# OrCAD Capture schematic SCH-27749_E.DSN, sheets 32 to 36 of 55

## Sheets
32 DDR #2 DIMM: size C
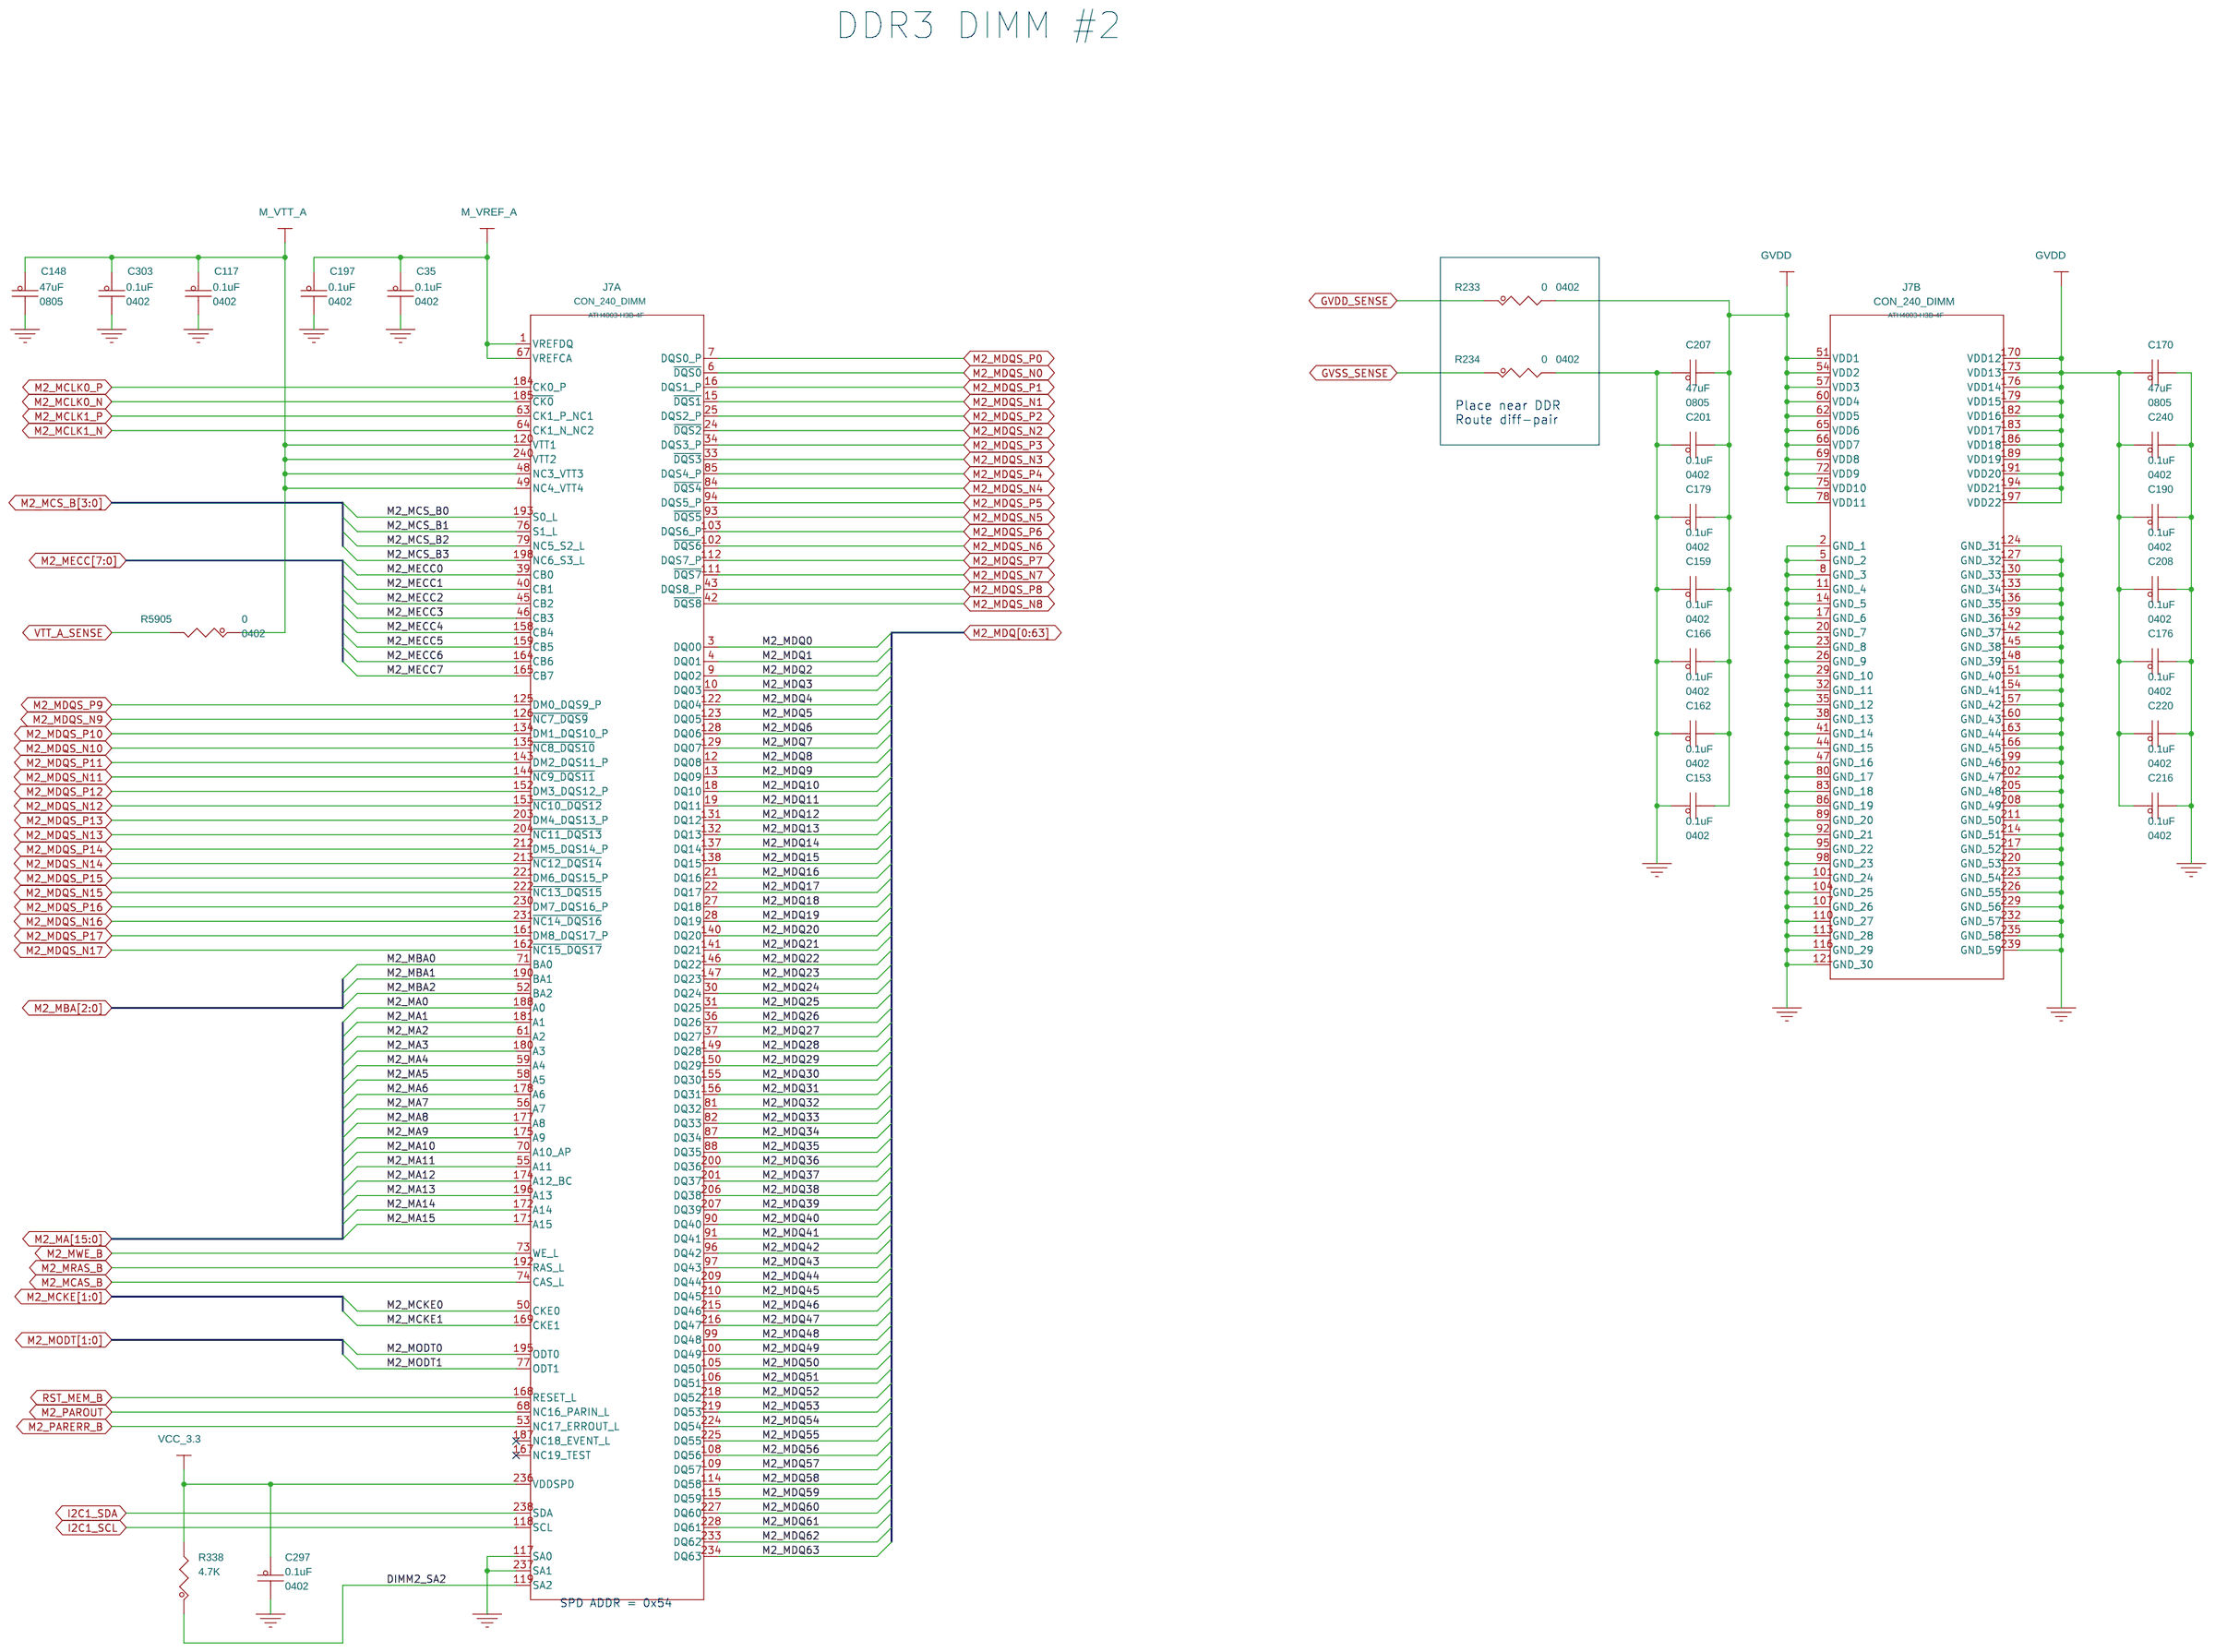
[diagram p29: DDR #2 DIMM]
33 DDR #3 DIMM: size C
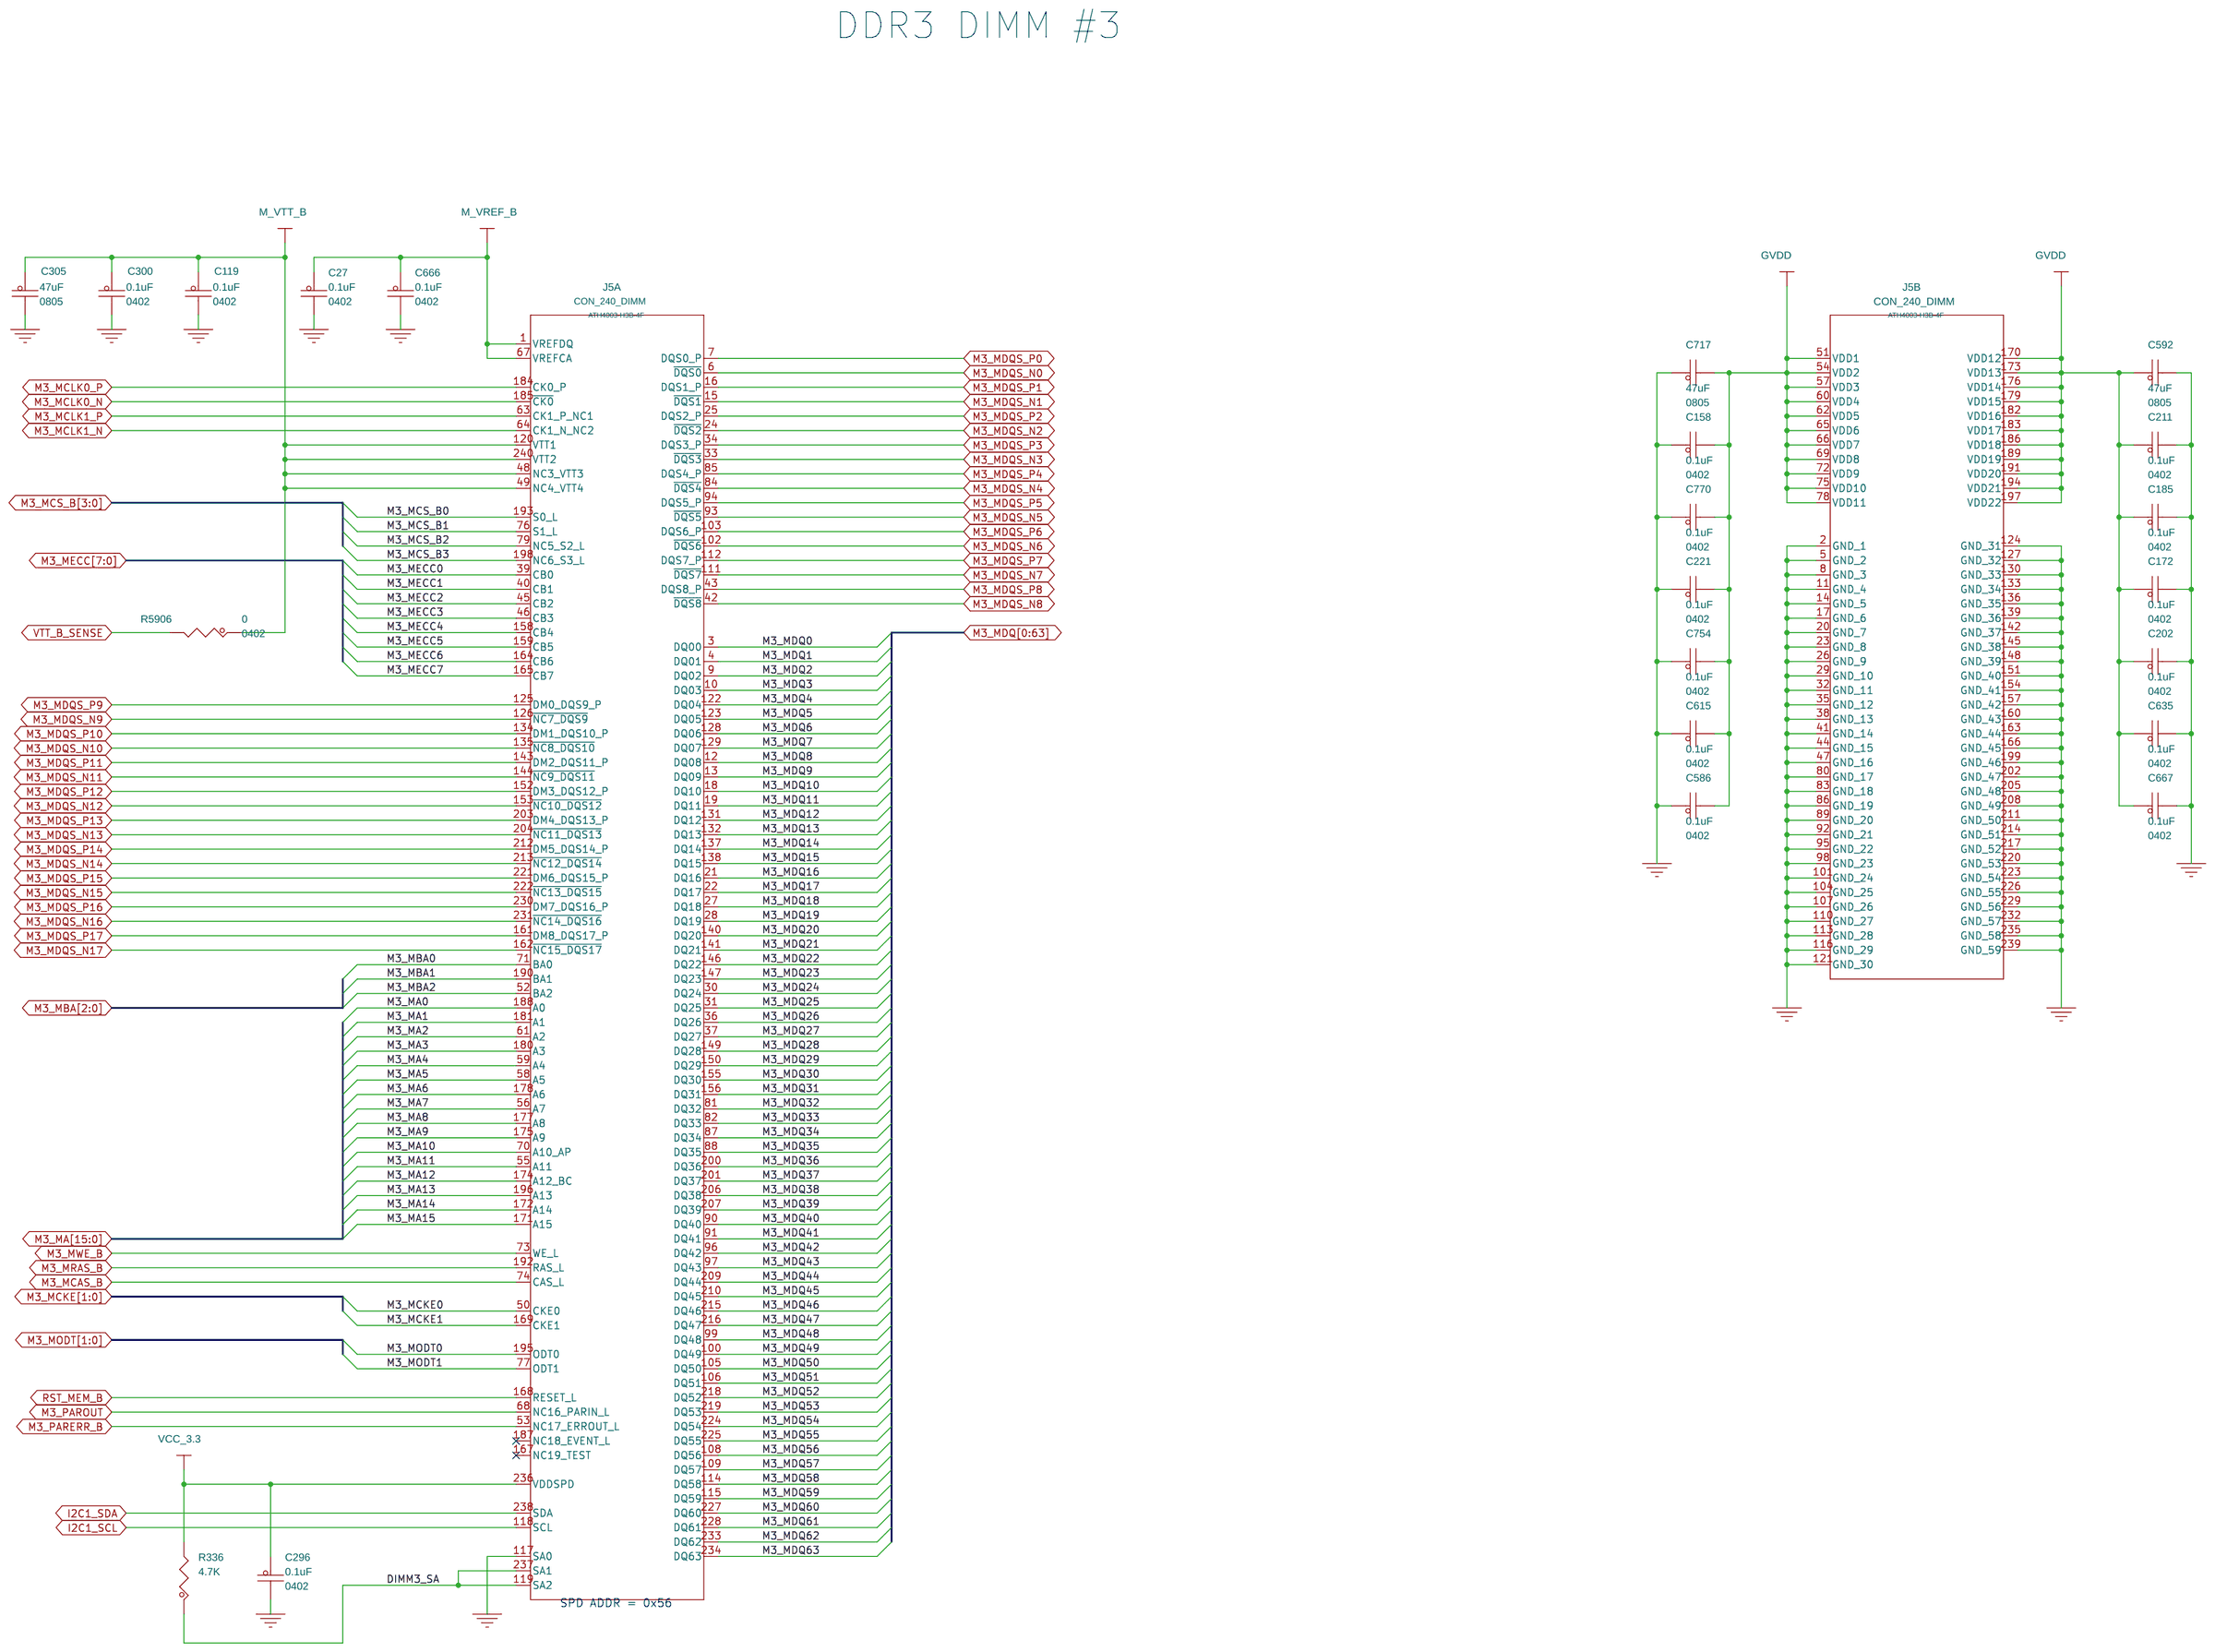
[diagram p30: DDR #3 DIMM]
34 T4240 Local Bus Block: size C
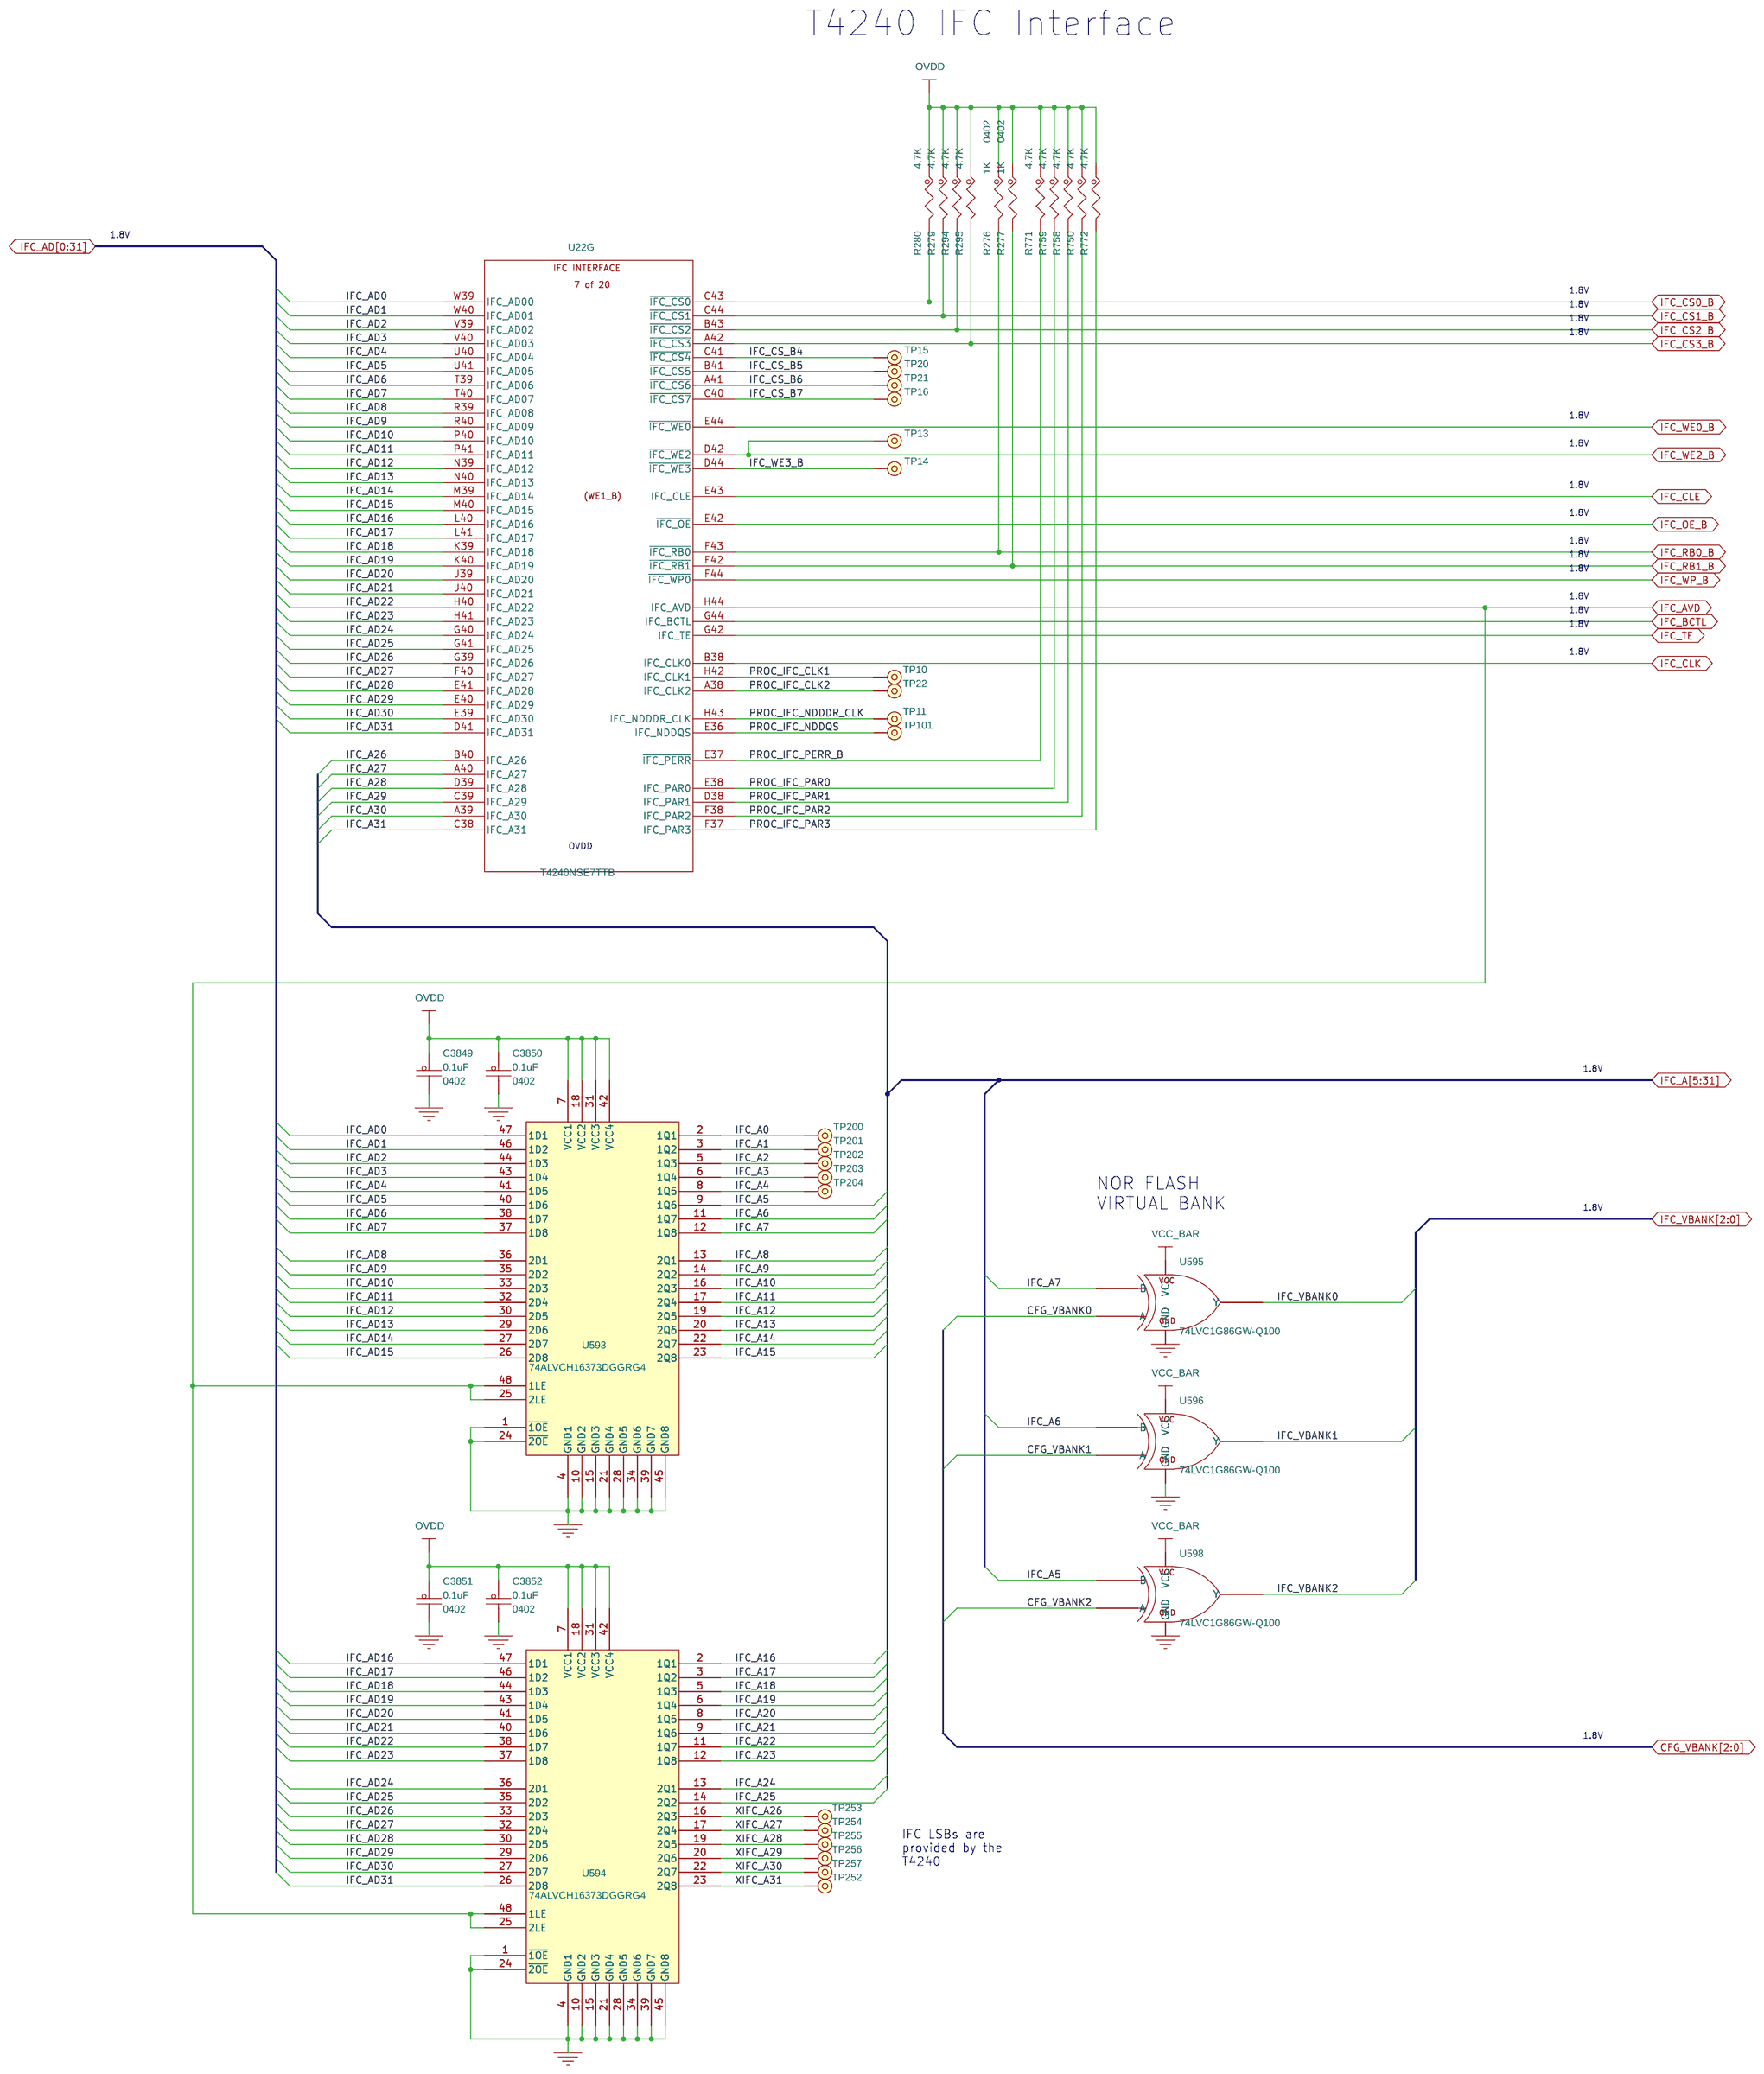
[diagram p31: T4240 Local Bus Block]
35 NOR & NAND Flash: size C
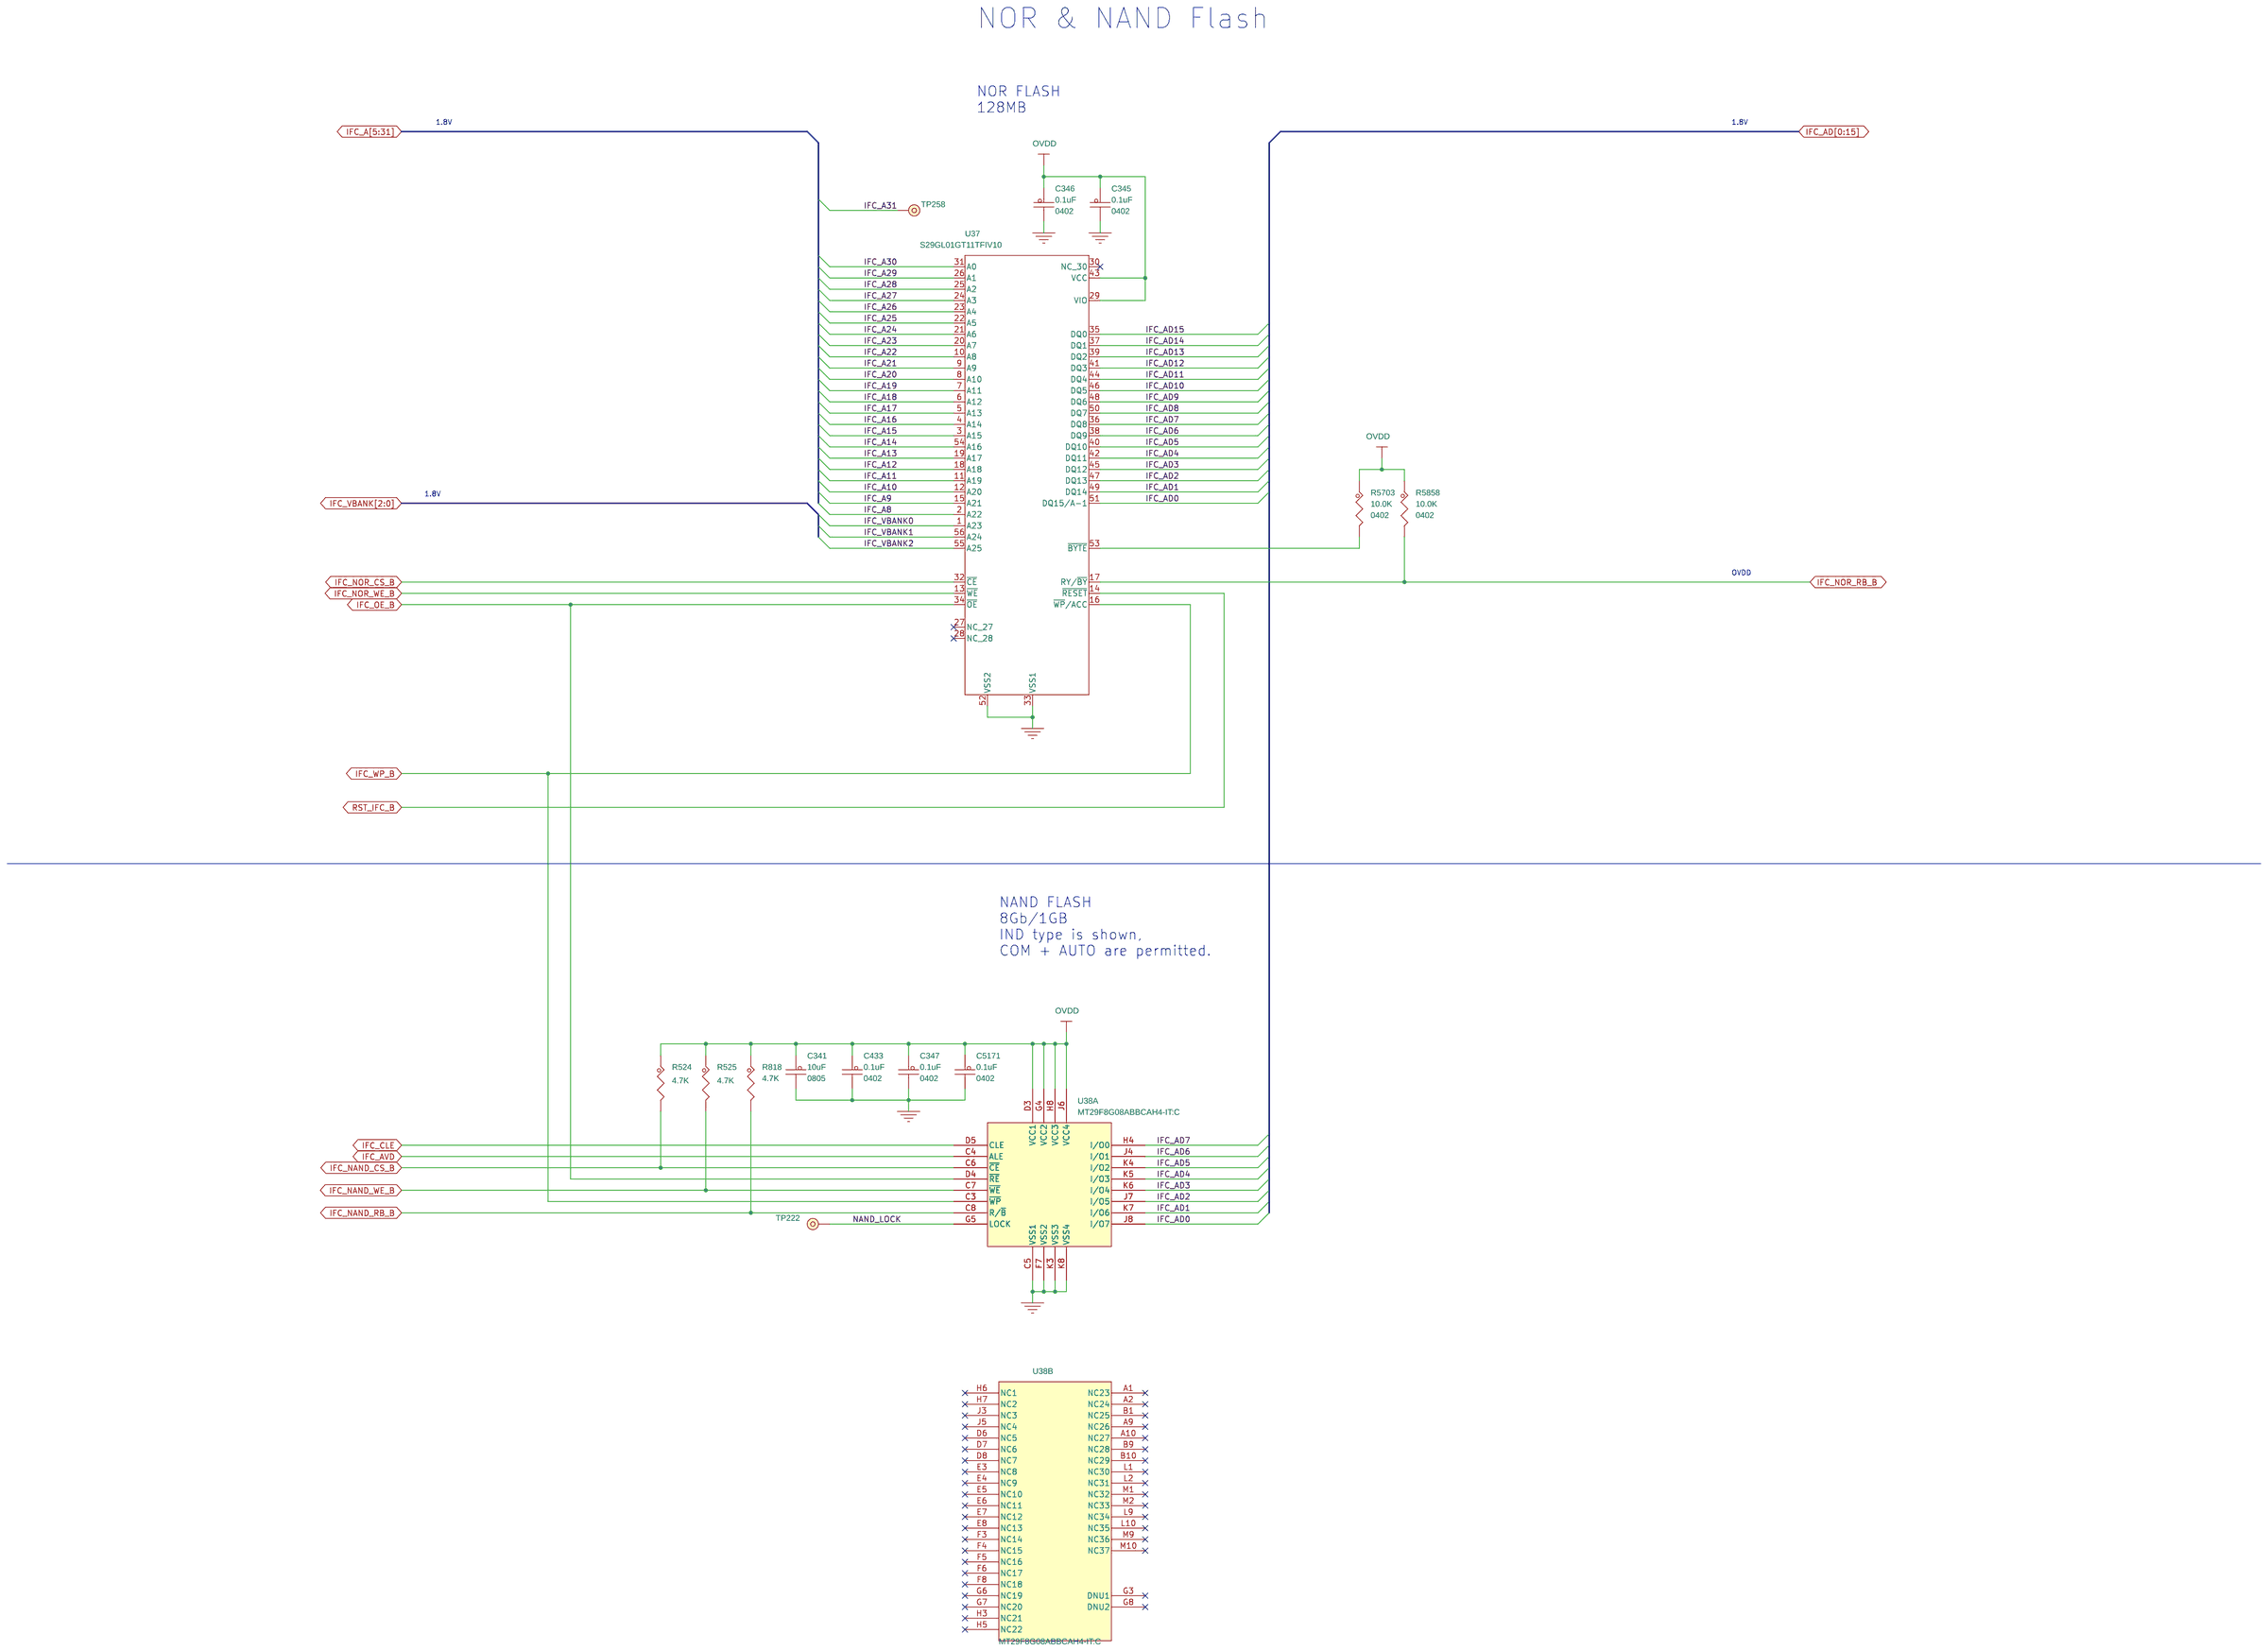
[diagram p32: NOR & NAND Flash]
36 T4240 SPI / SDHC Port: size C
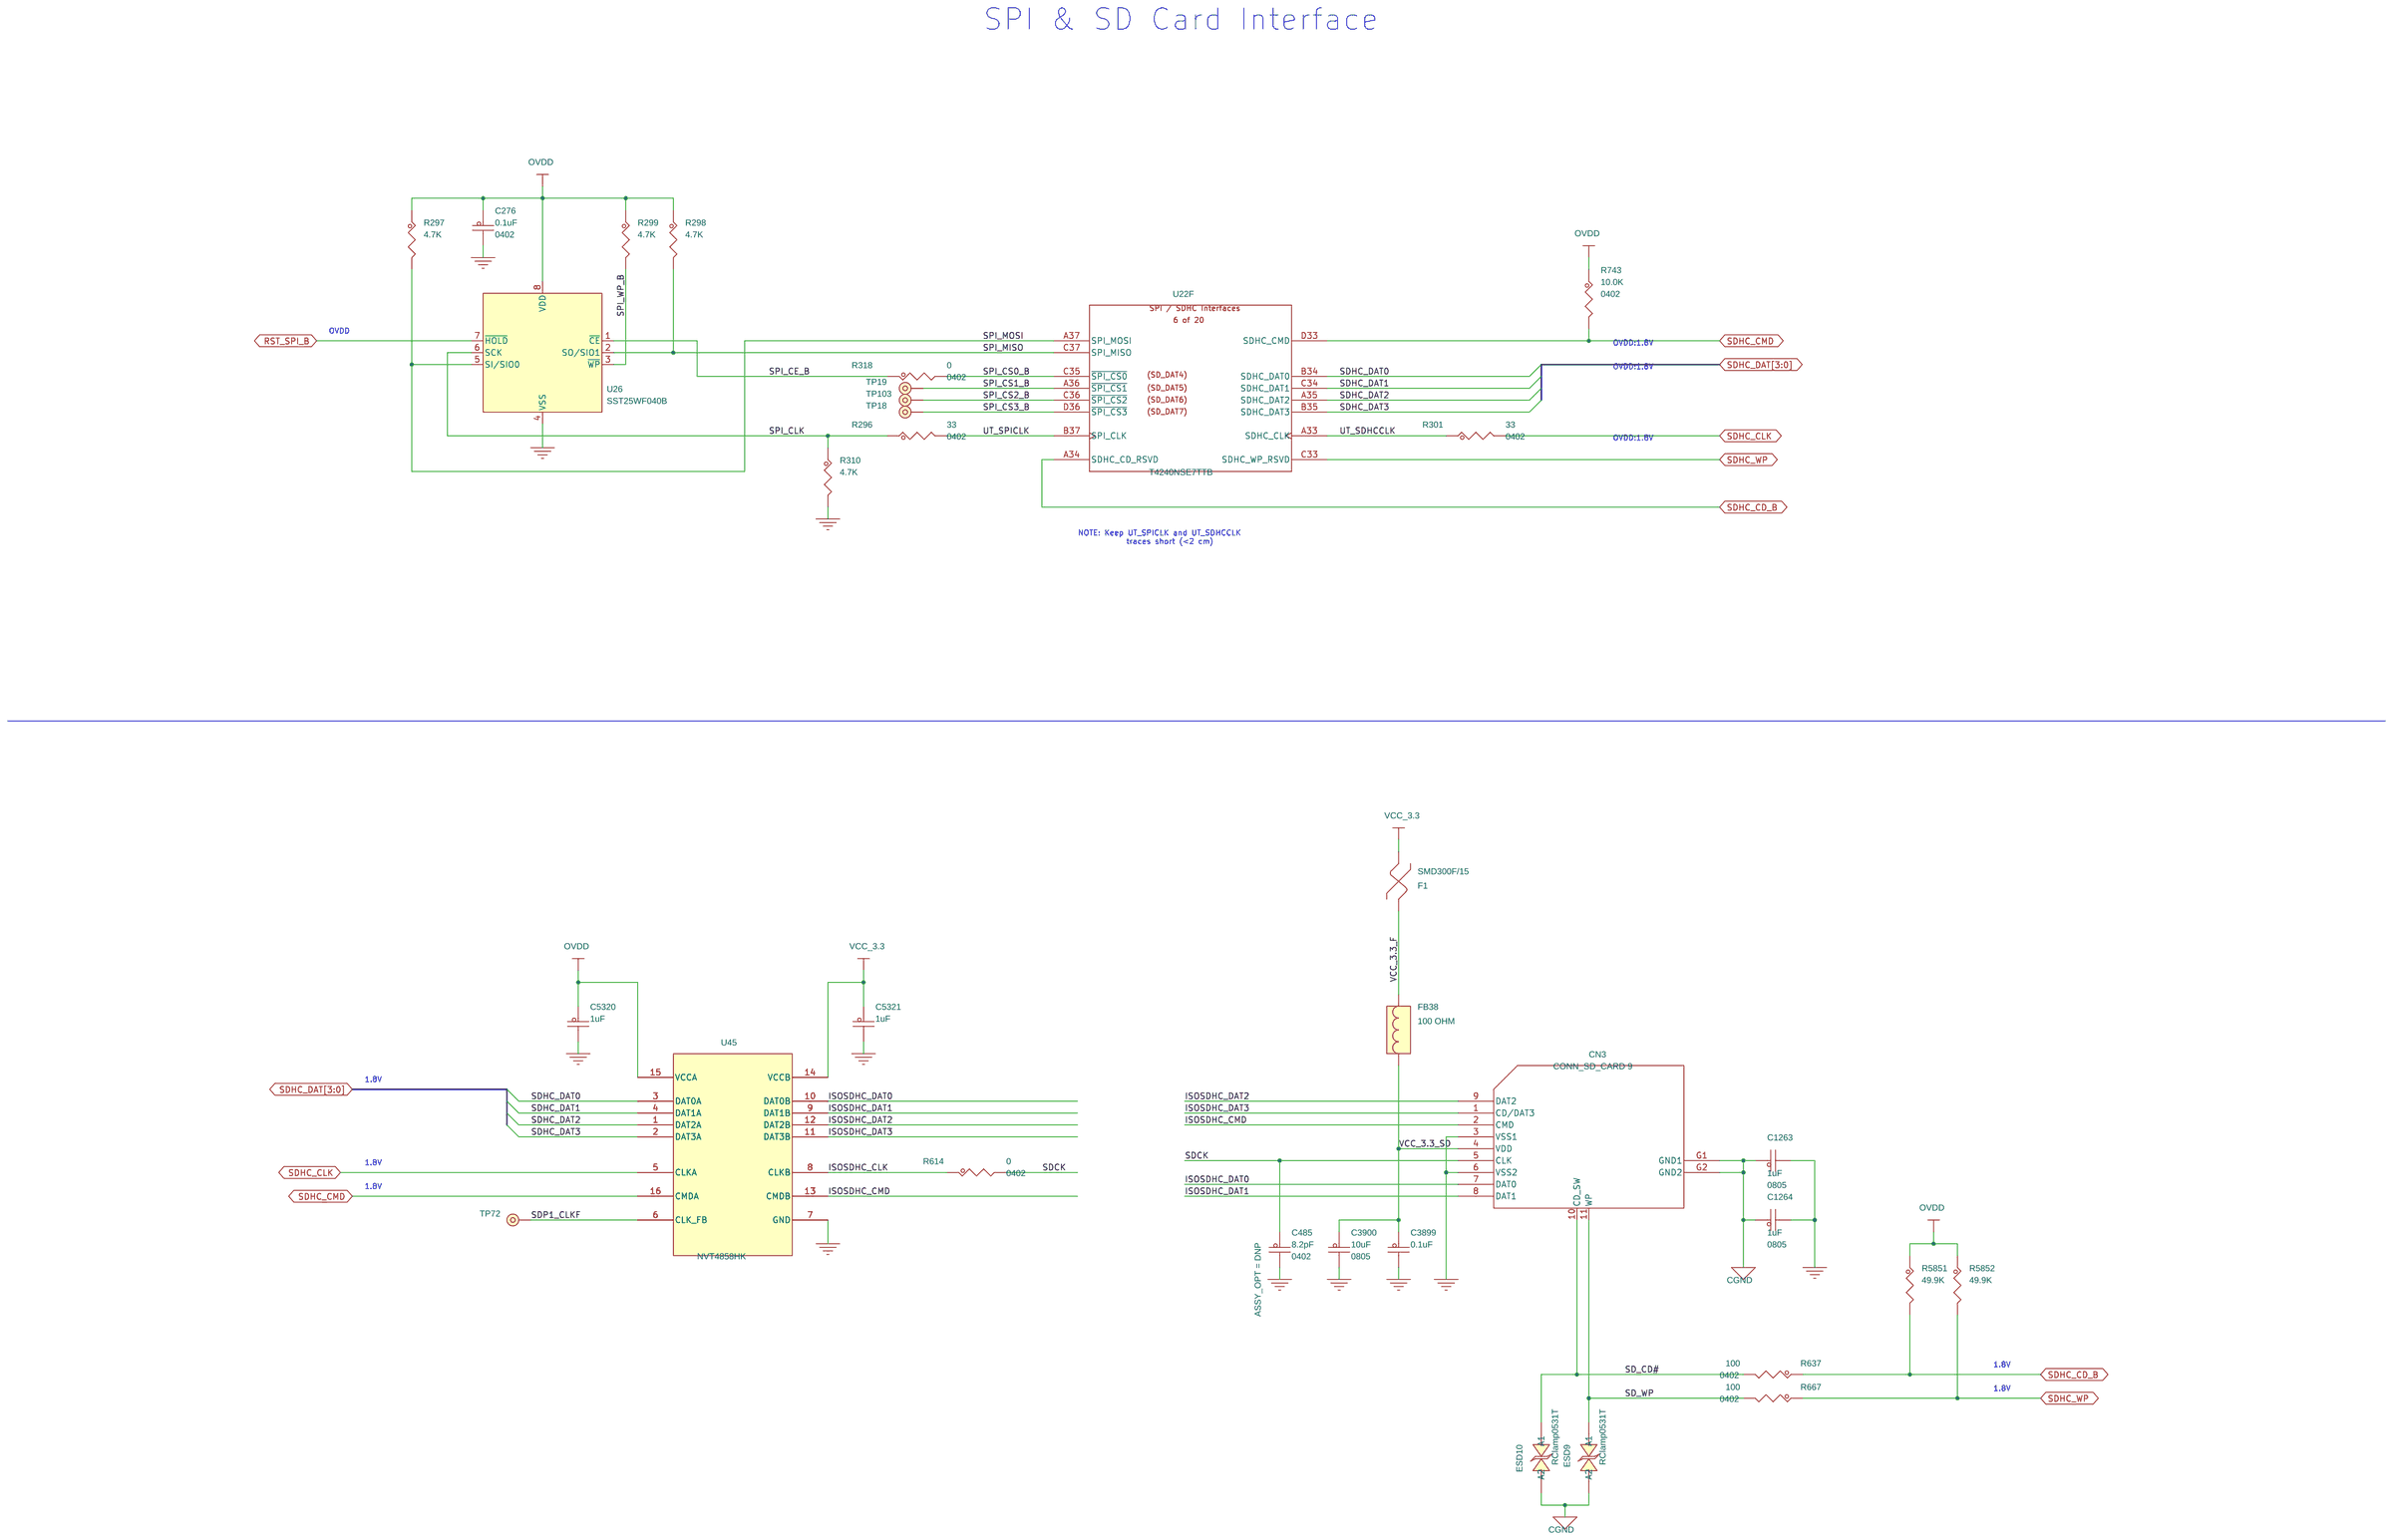
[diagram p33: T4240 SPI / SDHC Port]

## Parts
sheet DDR #2 DIMM
C35  0.1uF  [CC0402_HD]
C117  0.1uF  [CC0402_HD]
C148  47uF  [CC0805_OV]
C153  0.1uF  [CC0402_HD]
C159  0.1uF  [CC0402_HD]
C162  0.1uF  [CC0402_HD]
C166  0.1uF  [CC0402_HD]
C170  47uF  [CC0805_OV]
C176  0.1uF  [CC0402_HD]
C179  0.1uF  [CC0402_HD]
C190  0.1uF  [CC0402_HD]
C197  0.1uF  [CC0402_HD]
C201  0.1uF  [CC0402_HD]
C207  47uF  [CC0805_OV]
C208  0.1uF  [CC0402_HD]
C216  0.1uF  [CC0402_HD]
C220  0.1uF  [CC0402_HD]
C240  0.1uF  [CC0402_HD]
C297  0.1uF  [CC0402_HD]
C303  0.1uF  [CC0402_HD]
J7  CON_240_DIMM  [CON_240_DDR3_DIMM_SKT]  (sections A,B)
R233  0  [RC0402_25]
R234  0  [RC0402_25]
R338  4.7K  [RC0402_25]
R5905  0  [RC0402_25]
sheet DDR #3 DIMM
C27  0.1uF  [CC0402_HD]
C119  0.1uF  [CC0402_HD]
C158  0.1uF  [CC0402_HD]
C172  0.1uF  [CC0402_HD]
C185  0.1uF  [CC0402_HD]
C202  0.1uF  [CC0402_HD]
C211  0.1uF  [CC0402_HD]
C221  0.1uF  [CC0402_HD]
C296  0.1uF  [CC0402_HD]
C300  0.1uF  [CC0402_HD]
C305  47uF  [CC0805_OV]
C586  0.1uF  [CC0402_HD]
C592  47uF  [CC0805_OV]
C615  0.1uF  [CC0402_HD]
C635  0.1uF  [CC0402_HD]
C666  0.1uF  [CC0402_HD]
C667  0.1uF  [CC0402_HD]
C717  47uF  [CC0805_OV]
C754  0.1uF  [CC0402_HD]
C770  0.1uF  [CC0402_HD]
J5  CON_240_DIMM  [CON_240_DDR3_DIMM_SKT]  (sections A,B)
R336  4.7K  [RC0402_25]
R5906  0  [RC0402_25]
sheet NOR & NAND Flash
C341  10uF  [CC0603_OV]
C345  0.1uF  [CC0402_HD]
C346  0.1uF  [CC0402_HD]
C347  0.1uF  [CC0402_HD]
C433  0.1uF  [CC0402_HD]
C5171  0.1uF  [CC0402_HD]
R524  4.7K  [RC0402_25]
R525  4.7K  [RC0402_25]
R818  4.7K  [RC0402_25]
R5703  10.0K  [RC0402_25]
R5858  10.0K  [RC0402_25]
TP222  TPAD_020  [tpad_020_top]
TP258  TPAD_020  [tpad_020_top]
U37  S29GL01GT11TFIV10  [TSOP56_0P5_14X18]
U38  MT29F8G08ABBCAH4-IT:C  [vfbga63_0p8_9x11]  (sections A,B)
sheet T4240 DDR Controller #2
U22  T4240NSE7TTB  [BGA1932_1MM_45X45MM]  (sections A,B,C,D,E,F,G,H,I,J,K,L,M,N,O,P,Q,R,S,T)
sheet T4240 Local Bus Block
C3849  0.1uF  [CC0402_HD]
C3850  0.1uF  [CC0402_HD]
C3851  0.1uF  [CC0402_HD]
C3852  0.1uF  [CC0402_HD]
R276  1K  [RC0402_25]
R277  1K  [RC0402_25]
R279  4.7K  [RC0402_25]
R280  4.7K  [RC0402_25]
R294  4.7K  [RC0402_25]
R295  4.7K  [RC0402_25]
R750  4.7K  [RC0402_25]
R758  4.7K  [RC0402_25]
R759  4.7K  [RC0402_25]
R771  4.7K  [RC0402_25]
R772  4.7K  [RC0402_25]
TP10  TPAD_020  [tpad_020_top]
TP11  TPAD_020  [tpad_020_top]
TP13  TPAD_020  [tpad_020_top]
TP14  TPAD_020  [tpad_020_top]
TP15  TPAD_020  [tpad_020_top]
TP16  TPAD_020  [tpad_020_top]
TP20  TPAD_020  [tpad_020_top]
TP21  TPAD_020  [tpad_020_top]
TP22  TPAD_020  [tpad_020_top]
TP101  TPAD_020  [tpad_020_top]
TP200  TPAD_020  [tpad_020_top]
TP201  TPAD_020  [tpad_020_top]
TP202  TPAD_020  [tpad_020_top]
TP203  TPAD_020  [tpad_020_top]
TP204  TPAD_020  [tpad_020_top]
TP252  TPAD_020  [tpad_020_top]
TP253  TPAD_020  [tpad_020_top]
TP254  TPAD_020  [tpad_020_top]
TP255  TPAD_020  [tpad_020_top]
TP256  TPAD_020  [tpad_020_top]
TP257  TPAD_020  [tpad_020_top]
U593  74ALVCH16373DGGRG4  [TSSOP48_PH]
U594  74ALVCH16373DGGRG4  [TSSOP48_PH]
U595  74LVC1G86GW-Q100  [SC70-5]
U596  74LVC1G86GW-Q100  [SC70-5]
U598  74LVC1G86GW-Q100  [SC70-5]
sheet T4240 SPI / SDHC Port
C276  0.1uF  [CC0402_HD]
C485  8.2pF  [CC0402_25]
C1263  1uF  [CC0603_OV]
C1264  1uF  [CC0603_OV]
C3899  0.1uF  [CC0402_HD]
C3900  10uF  [CC0603_OV]
C5320  1uF  [CC0402_HD]
C5321  1uF  [CC0402_HD]
CN3  CONN_SD_CARD 9  [con_sdcard_28p9x29_sm_ra]
ESD9  RClamp0531T  [diode_bidir_0402]
ESD10  RClamp0531T  [diode_bidir_0402]
F1  SMD300F/15  [FUSE_SMD050]
FB38  100 OHM  [IND_0805]
R296  33  [RC0402_25]
R297  4.7K  [RC0402_25]
R298  4.7K  [RC0402_25]
R299  4.7K  [RC0402_25]
R301  33  [RC0402_25]
R310  4.7K  [RC0402_25]
R318  0  [RC0402_25]
R614  0  [RC0402_25]
R637  100  [RC0402_25]
R667  100  [RC0402_25]
R743  10.0K  [RC0402_25]
R5851  49.9K  [RC0402_25]
R5852  49.9K  [RC0402_25]
TP18  TPAD_020  [tpad_020_top]
TP19  TPAD_020  [tpad_020_top]
TP72  TPAD_020  [tpad_020_top]
TP103  TPAD_020  [tpad_020_top]
U26  SST25WF040B  [SO8_1P27_4X5]
U45  NVT4858HK  [xqfn16_0p4_2p7x1p9]

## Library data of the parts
C27 C35 C117 C119 C153 C158 C159 C162 C166 C172 C176 C179 C185 C190 C197 C201 C202 C208 C211 C216 C220 C221 C240 C276 C296 C297 C300 C303 C345-C347 C433 C586 C615 C635 C666 C667 C754 C770 C3849-C3852 C5171 = CAP_NP: CAP CER 0.1uF 16V 10% X7R AEC-Q200 0402; AGILE_PN: 150-79025; CAD_APPROVED: Yes; FPLIST: CC0402_25,CC0402_HD,0402_CC,capc0402_l; HEIGHT: 0.55MM; MFG_NAME01: MURATA; MFG_PN01: GCM155R71C104KA55D; Package: 0402; Package Size: 0402; Package Type: ø180mm Reel PAPER; Part Number: 4CC104B163X00; Product Name: (H)MLCC 0.1uF/16V +-10% 0402 X7R; ROHS: Yes; Rated Voltage: 16V; Temp Range: -55C to +125C; Tolerance: 10%
C148 C170 C207 C305 C592 C717 = CAP_NP: CAP CER 47uF 6.3V 20% X5R AEC-Q200 0805; AGILE_PN: 150-80462; CAD_APPROVED: Yes; FPLIST: CC0805_OV,CC0805,0805_CC; HEIGHT: 1.45MM; MFG_NAME01: MURATA; MFG_PN01: GRT21BR60J476ME13L; Package: 0805; Package Size: 2x1.25MM; Package Type: 0805; Part Number: 4CC476D631X00; Product Name: (H)MLCC 47uF/6.3V +-20% 0805 X5R; ROHS: Yes; Rated Voltage: 6.3V; Temp Range: -55C to +85C; Tolerance: 20%
J7 = DDR3_240P: CON 240 DIMM DDR3 1.5V SKT TH 1MM SP 910H .125 THK PCB AU 125L; AGILE_PN: 210-77672; CAD_APPROVED: Yes; CDS_LIB: fcl_connector; COMP_HEIGHT: 23.10 MM; CPN: TMP-WF-6058; CaptureCellPackProp: DDR3_240PA; DRAWING: @EXPEDITION_LIB.EXPEDITION(SCH_1):PAGE33; GROUP: DIMM4; HEIGHT: 23.10 MM; LOCATION: J22; MFG_NAME: FOXCONN; MFG_NAME01: FOXCONN; MFG_PN: ATH4003-H3B-4F; MFG_PN01: ATH4003-H3B-4F; PHYS_PAGE: 33; Part Number: 4SRD324006X00; Product Name: DDR3 DIMM SOCKET 240PIN FOXCONN:ATH4017-P3B-4F; ROHS: Yes; ROT: 0; XY: (-5700,2625)
R233 R234 R318 R614 R5905 R5906 = RES: RES MF ZERO OHM 1/10W -- 0402; AGILE_PN: 470-79965; CAD_APPROVED: Yes; FPLIST: RC0402_25,RC0402_HD,RC0402_X2,0402_CC,RC0402_X3; HEIGHT: 0.4MM; MFG_NAME01: PANASONIC; MFG_PN01: ERJ-2GE0R00X; Package: 0402; Part Number: 4RC0000B51X00; Product Name: (H)RES 0E 1/16W 0402 5% PBFREE; ROHS: Yes; Temp Range: –55 °C to +155 °C
R279 R280 R294 R295 R297-R299 R310 R336 R338 R524 R525 R750 R758 R759 R771 R772 R818 = RES: RES MF 4.7K 1/10W 5% AEC-Q200 0402; AGILE_PN: 470-82064; CAD_APPROVED: Yes; FPLIST: RC0402_25,RC0402_HD,0402_CC,RC0402_X2; HEIGHT: 0.41mm; MFG_NAME01: KOA SPEER; MFG_PN01: RK73B1ETTP472J; ROHS: Yes; Temp Range: -55C to +155C; Tolerance: 5%
J5 = DDR3_240P: CON 240 DIMM DDR3 1.5V SKT TH 1MM SP 910H .125 THK PCB AU 125L; AGILE_PN: 210-77672; CAD_APPROVED: Yes; CDS_LIB: fcl_connector; COMP_HEIGHT: 23.10 MM; CPN: TMP-WF-6058; CaptureCellPackProp: DDR3_240PA; DRAWING: @EXPEDITION_LIB.EXPEDITION(SCH_1):PAGE33; GROUP: DIMM6; HEIGHT: 23.10 MM; LOCATION: J22; MFG_NAME: FOXCONN; MFG_NAME01: FOXCONN; MFG_PN: ATH4003-H3B-4F; MFG_PN01: ATH4003-H3B-4F; PHYS_PAGE: 33; Part Number: 4SRD324006X00; Product Name: DDR3 DIMM SOCKET 240PIN FOXCONN:ATH4017-P3B-4F; ROHS: Yes; ROT: 0; XY: (-5700,2625)
C341 C3900 = CAP_NP: CAP CER 10UF 10V 10% X5R 0603; AGILE_PN: 150-78675; CAD_APPROVED: Yes; FPLIST: CC0603_OV,CC0603,0603_CC_NSP; HEIGHT: 1.016MM; MFG_NAME01: MURATA; MFG_PN01: GRM188R61A106KE69D; Package: 0805; Part Number: 4CC106D101X00; Product Name: (H)MLCC 10uF/10V +/-10% 0805 X5R; ROHS: Yes; Rated Voltage: 10V; Temp Range: -55C to +85C; Tolerance: 10%
R743 R5703 R5858 = RES: RES MF 10.0K 1/16W 1% AEC-Q200 0402; AGILE_PN: 470-75416; CAD_APPROVED: Yes; FPLIST: RC0402_25,RC0402_HD,0402_CC; HEIGHT: 0.4MM; MFG_NAME01: KOA SPEER; MFG_PN01: RK73H1ETTP1002F; Package: 0402; Part Number: 4RC1003B11X00; Product Name: (H)RES 10K 1/16W 0402 1% PBFREE; ROHS: Yes; Temp Range: –55 °C to +155 °C; Tolerance: 1%
TP10 TP11 TP13-TP16 TP18-TP22 TP72 TP101 TP103 TP200-TP204 TP222 TP252-TP258 = T_POINT_TH: TEST POINT PAD 20 MILS SMT, NOT PART TO ORDER; AGILE_PN: 211-81036; CAD_APPROVED: Yes; FPLIST: tpad_020_top,tpad_020_btm_nsp; HEIGHT: 0.127MM; MFG_NAME01: NO PART ORDER; MFG_PN01: NA; ROHS: Yes
U37 = S29GL01GP: IC MEM FLASH NOR 1GB 110NS 1.65-3.6V TSOP56; 3D_Mechanical_Footprint_File: http://fcl.am.freescale.net/ALLEGRO/step/tsop56_0p5_14x18.step; AGILE_PN: 342-00735; CAD_APPROVED: Yes; HEIGHT: 1.2MM; MFG_NAME01: CYPRESS SEMICONDUCTOR; ROHS: Yes; Temp Range: -40C to +85C; VOLTAGE: 1.65-3.6V
U38 = MT29F4G08ABBDAH4: IC MEM NAND FLASH 8Gb 8BIT 1.8V VFBGA63; 3D_Mechanical_Footprint_File: http://fcl.am.freescale.net/ALLEGRO/step/vfbga63_0p8_9x11.STEP; AGILE_PN: 334-82922; CAD_APPROVED: Yes; HEIGHT: 1.1 MM; MFG_NAME01: Micron; Package Size: VFBGA-63; ROHS: Yes; Temp Range: –40°C to +85°C
U22 = T4240: IC MPU 64BIT T4240 1.8GHz 1.025V CRYPTO QorIQ PBGA1932; 3D_Mechanical_Footprint_File: http://fcl.am.freescale.net/ALLEGRO/step/bga1932_1mm_45x45mm.STEP; AGILE_PN: 330-77243; CAD_APPROVED: Yes; HEIGHT: 3.33 MM; MFG_NAME01: NXP SEMICONDUCTOR; Package Size: SOT1645-1; Part Number: 71F101G206X01; Product Name: (N)SOC FREESCALE:T4240NSE7TTB; ROHS: Yes; Temp Range: 0 to 105 °C
R276 R277 = RES: RES 1K 1/16W 5% 0402; AGILE_PN: 470-80721; CAD_APPROVED: Yes; FPLIST: RC0402_25,RC0402_HD,0402_CC; HEIGHT: 0.4 MM; MFG_NAME01: TE CONNECTIVITY LTD; MFG_PN01: CRG0402J1K0; Package: 0402; Part Number: 4RC1002B11X00; Product Name: (H)RES 1K 1/16W 0402 1% PBFREE; ROHS: Yes; Tolerance: 5%
U593 U594 = 74ALVCH16373DGGRG4: IC REG D 16BIT TS 1.6-3.6V TSSOP48; 3D_Mechanical_Footprint_File: http://fcl.am.freescale.net/ALLEGRO/step/tssop48_ph.STEP; AGILE_PN: 312-79574; CAD_APPROVED: Yes; HEIGHT: 1.2MM; MFG_NAME01: TEXAS INSTRUMENTS; ROHS: Yes; VOLTAGE: 1.6-3.6V
U595 U596 U598 = 74AUP1G86GW: IC GATE XOR 1CH 2-INP 1.65-5.5V AEC-Q100 SOT353-1; 3D_Mechanical_Footprint_File: http://fcl.am.freescale.net/ALLEGRO/step/sc70-5.STEP; AGILE_PN: 312-81701; CAD_APPROVED: Yes; HEIGHT: 1.1MM; MFG_NAME01: NEXPERIA; ROHS: Yes; VOLTAGE: 1.65-5.5V
C485 = CAP_NP: CAP CER 8.2pF 50V C0G 0.5pF 0402; AGILE_PN: 150-79777; ASSY_OPT: DNP; CAD_APPROVED: Yes; FPLIST: CC0402_25,CC0402_HD,0402_CC,capc0402_l; HEIGHT: 0.55MM; MFG_NAME01: YAGEO; MFG_PN01: CC0402DRNPO9BN8R2; Package: 0402; Part Number: 4CC080B501X00; Product Name: (H)MLCC 8.2pF/50V +-0.5pF 0402 NPO; ROHS: Yes; Rated Voltage: 50V; Temp Range: -55C to +125C; Tolerance: 0.5pF
C1263 C1264 = CAP_NP: CAP CER 1UF 25V 10% X7R 0603; AGILE_PN: 150-30185; CAD_APPROVED: Yes; FPLIST: CC0603_OV,CC0603,0603_CC; HEIGHT: 0.9mm; MFG_NAME01: WURTH ELEKTRONIK EISOS GMBH & CO. KG (ELECTRONIC & ELECTROMEHANICAL COMP); MFG_PN01: 885012206076; Package: 0805; Package Size: 0603; Package Type: tape & reel; Part Number: 4CC105D162X00; Product Name: (H)MLCC 1uF/16V +-10% 0805 X5R PBFREE; ROHS: Yes; Rated Voltage: 25V; Temp Range: -55C to +125C; Tolerance: 10%
C3899 = CAP_NP: CAP CER 0.1uF 16V 10% X7R AEC-Q200 0402; AGILE_PN: 150-79025; CAD_APPROVED: Yes; FPLIST: CC0402_25,CC0402_HD,0402_CC,capc0402_l; HEIGHT: 0.55MM; MFG_NAME01: MURATA; MFG_PN01: GCM155R71C104KA55D; Package Size: 0402; Package Type: ø180mm Reel PAPER; ROHS: Yes; Rated Voltage: 16V; Temp Range: -55C to +125C; Tolerance: 10%
C5320 C5321 = CAP_NP: CAP CER 1uF 10V 10% X7S 0402; AGILE_PN: 150-80357; CAD_APPROVED: Yes; FPLIST: CC0402_25,CC0402_HD,0402_CC,capc0402_l; HEIGHT: 0.6MM; MFG_NAME01: MURATA; MFG_PN01: GRM155C71A105KE11D; Package Size: 0402; ROHS: Yes; Rated Voltage: 10V; SIGNAL_MODEL: DEFAULT_CAPACITOR_1e+06pF_2_1; Temp Range: -55C to +125C; Tolerance: 10%; VOLTAGE: 10V
CN3 = CONN_SDCARD_PUSH_PULL_9P_SH2: CON 9 SD CARD PUSH-PULL SKT SMT RA 2.5MM SP 120H AU; 3D_Mechanical_Footprint_File: http://fcl.am.freescale.net/ALLEGRO/step/con_sdcard_28p9x29_sm_ra.STEP; AGILE_PN: 211-80186; CAD_APPROVED: Yes; HEIGHT: 3.05 MM; MFG_NAME01: WURTH ELEKTRONIK EISOS GMBH & CO. KG (ELECTRONIC & ELECTROMEHANICAL COMP); MFG_PN01: 693061010911; ROHS: Yes; Temp Range: -25°C to +85°C; Temp_Range: -25°C to +85°C
ESD9 ESD10 = DIODE_TVS_BIDIR: DIODE TVS ESD PROTECTION 40A 5V 0402; 3D_Mechanical_Footprint_File: http://fcl.am.freescale.net/ALLEGRO/step/diode_bidir_0402_17h.STEP; AGILE_PN: 480-78560; CAD_APPROVED: Yes; HEIGHT: 0.43MM; MFG_NAME01: SEMTECH CORP; MFG_PN01: RClamp0531T.TCT; Rated Voltage: 5V
F1 = FUSE_RESETTABLE: FUSE PLYSW 3A 15V SMT; 3D_Mechanical_Footprint_File: http://fcl.am.freescale.net/ALLEGRO/step/FUSE_SMD050.STEP; AGILE_PN: 510-77803; CAD_APPROVED: Yes; HEIGHT: 3MM; MFG_NAME01: LITTELFUSE; MFG_PN01: SMD300F/15-2; ROHS: Yes
FB38 = BEAD: IND FER BEAD 100OHM@100MHZ 4A 25% AEC-Q200 0805; AGILE_PN: 180-78923; CAD_APPROVED: Yes; HEIGHT: 1.05MM; MFG_NAME01: TDK; MFG_PN01: MPZ2012S101ATD25; Package Size: 2x1.25MM; ROHS: Yes; Temp Range: -55°C to +125°C
R296 R301 = RES: RES MF 33 OHM 1/10W 5% AEC-Q200 0402; AGILE_PN: 470-82134; CAD_APPROVED: Yes; FPLIST: RC0402_25,RC0402_HD,0402_CC; HEIGHT: 0.4MM; MFG_NAME01: KOA SPEER; MFG_PN01: RK73B1ETTP330J; Package: 0402; Part Number: 4RC3300B11X00; Product Name: (H)RES 33E 1/16W 0402 1% PBFREE; ROHS: Yes; Temp Range: -55&#8451; to 155&#8451;; Tolerance: 5%
R637 R667 = RES: RES MF 100 OHM 1/16W 1% AEC-Q200 0402; AGILE_PN: 470-80666; CAD_APPROVED: Yes; FPLIST: RC0402_25,RC0402_HD,0402_CC; HEIGHT: 0.4 MM; MFG_NAME01: KOA SPEER; MFG_PN01: RK73H1ETTP1000F; Package: 0402; Part Number: 4RC1001B11X00; Product Name: (H)RES 100E 1/16W 0402 1% PBFREE; ROHS: Yes
R5851 R5852 = RES: RES MF 49.9K 1/16W 1% 0402; AGILE_PN: 470-76043; CAD_APPROVED: Yes; FPLIST: RC0402_25,RC0402_HD,0402_CC; HEIGHT: 0.4MM; MFG_NAME01: BOURNS; MFG_PN01: CR0402-FX-4992GLF; ROHS: Yes; ROOM: PS_VDD_GVDD; Tolerance: 1%
U26 = SST25WF040B_SOIC8: IC MEM FLASH SERIAL 4MBIT 1.65-1.95V SOIC8; 3D_Mechanical_Footprint_File: http://fcl.am.freescale.net/ALLEGRO/step/so8_1p27_4x5.step; AGILE_PN: 334-77558; CAD_APPROVED: Yes; HEIGHT: 1.75 MM; MFG_NAME01: MICROCHIP TECHNOLOGY INC; MFG_PN01: SST25WF040B-40I-SN; ROHS: Yes; VOLTAGE: 1.65-1.95V
U45 = NVT4858HK_QFN16: IC BI VXLTR 208MHZ 1.65-3.6V XQFN16; 3D_Mechanical_Footprint_File: http://fcl.am.freescale.net/ALLEGRO/step/xqfn16_0p4_2p7x1p9.STEP; AGILE_PN: TMP-CIP-4486; CAD_APPROVED: Yes; HEIGHT: 0.5 MM; MFG_NAME01: NXP; PRE_APN: 312-82857; ROHS: Yes; Temp Range: -40 °C to +85 °C; VOLTAGE: 1.65-3.6V

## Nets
GND: C27.2 C35.2 C117.2 C119.2 C148.2 C153.1 C158.1 C159.1 C162.1 C166.1 C170.2 C172.2 C176.2 C179.1 C185.2 C190.2 C197.2 C201.1 C202.2 C207.1 C208.2 C211.2 C216.2 C220.2 C221.1 C240.2 C276.2 C296.2 C297.2 C300.2 C303.2 C305.2 C341.2 C345.2 C346.2 C347.2 C433.2 C485.2 C586.1 C592.2 C615.1 C635.2 C666.2 C667.2 C717.1 C754.1 C770.1 C1263.2 C1264.2 C3849.2 C3850.2 C3851.2 C3852.2 C3899.2 C3900.2 C5171.2 C5320.2 C5321.2 CN3.3(VSS1) CN3.6(VSS2) J5.2(GND_1) J5.5(GND_2) J5.8(GND_3) J5.11(GND_4) J5.14(GND_5) J5.17(GND_6) J5.20(GND_7) J5.23(GND_8) J5.26(GND_9) J5.29(GND_10) J5.32(GND_11) J5.35(GND_12) J5.38(GND_13) J5.41(GND_14) J5.44(GND_15) J5.47(GND_16) J5.80(GND_17) J5.83(GND_18) J5.86(GND_19) J5.89(GND_20) J5.92(GND_21) J5.95(GND_22) J5.98(GND_23) J5.101(GND_24) J5.104(GND_25) J5.107(GND_26) J5.110(GND_27) J5.113(GND_28) J5.116(GND_29) J5.117(SA0) J5.121(GND_30) J5.124(GND_31) J5.127(GND_32) J5.130(GND_33) J5.133(GND_34) J5.136(GND_35) J5.139(GND_36) J5.142(GND_37) J5.145(GND_38) J5.148(GND_39) J5.151(GND_40) J5.154(GND_41) J5.157(GND_42) J5.160(GND_43) J5.163(GND_44) J5.166(GND_45) J5.199(GND_46) J5.202(GND_47) J5.205(GND_48) J5.208(GND_49) J5.211(GND_50) J5.214(GND_51) J5.217(GND_52) J5.220(GND_53) J5.223(GND_54) J5.226(GND_55) J5.229(GND_56) J5.232(GND_57) J5.235(GND_58) J5.239(GND_59) J7.2(GND_1) J7.5(GND_2) J7.8(GND_3) J7.11(GND_4) J7.14(GND_5) J7.17(GND_6) J7.20(GND_7) J7.23(GND_8) J7.26(GND_9) J7.29(GND_10) J7.32(GND_11) J7.35(GND_12) J7.38(GND_13) J7.41(GND_14) J7.44(GND_15) J7.47(GND_16) J7.80(GND_17) J7.83(GND_18) J7.86(GND_19) J7.89(GND_20) J7.92(GND_21) J7.95(GND_22) J7.98(GND_23) J7.101(GND_24) J7.104(GND_25) J7.107(GND_26) J7.110(GND_27) J7.113(GND_28) J7.116(GND_29) J7.117(SA0) J7.121(GND_30) J7.124(GND_31) J7.127(GND_32) J7.130(GND_33) J7.133(GND_34) J7.136(GND_35) J7.139(GND_36) J7.142(GND_37) J7.145(GND_38) J7.148(GND_39) J7.151(GND_40) J7.154(GND_41) J7.157(GND_42) J7.160(GND_43) J7.163(GND_44) J7.166(GND_45) J7.199(GND_46) J7.202(GND_47) J7.205(GND_48) J7.208(GND_49) J7.211(GND_50) J7.214(GND_51) J7.217(GND_52) J7.220(GND_53) J7.223(GND_54) J7.226(GND_55) J7.229(GND_56) J7.232(GND_57) J7.235(GND_58) J7.237(SA1) J7.239(GND_59) R234.2 R310.2 U26.4(VSS) U37.33(VSS1) U37.52(VSS2) U38.C5(VSS1) U38.F7(VSS2) U38.K3(VSS3) U38.K8(VSS4) U45.7(GND) U593.1(~{1OE}) U593.4(GND1) U593.10(GND2) U593.15(GND3) U593.21(GND4) U593.24(~{2OE}) U593.28(GND5) U593.34(GND6) U593.39(GND7) U593.45(GND8) U594.1(~{1OE}) U594.4(GND1) U594.10(GND2) U594.15(GND3) U594.21(GND4) U594.24(~{2OE}) U594.28(GND5) U594.34(GND6) U594.39(GND7) U594.45(GND8) U595.3(GND) U596.3(GND) U598.3(GND) ; also on sheet 6 7 8 9 10 11 12 13 14 15 16 18 19 20 21 22 24 25 27 28 29 30 31 37 38 39 40 41 42 43 44 45 46 47 48 49 50 51 52 53 54
VCC_3.3: C296.1 C297.1 C5321.1 F1.1 J5.236(VDDSPD) J7.236(VDDSPD) R336.2 R338.2 U45.14(VCCB) ; also on sheet 6 12 13 16 18 24 25 31 39 40 41 42 43 44 47 48 49 50 51 53
VCC_3.3_F: F1.2 FB38.2
VCC_3.3_SD: C3899.1 C3900.1 CN3.4(VDD) FB38.1
CFG_VBANK0: U595.2(A) ; also on sheet 8
CFG_VBANK1: U596.2(A) ; also on sheet 8
CFG_VBANK2: U598.2(A) ; also on sheet 8
CGND: C1263.1 C1264.1 CN3.G1(GND1) CN3.G2(GND2) ESD9.2(A2) ESD10.2(A2) ; also on sheet 40 44 49 52
DIMM2_SA2: J7.119(SA2) R338.1
DIMM3_SA: J5.119(SA2) J5.237(SA1) R336.1
GVDD: C153.2 C158.2 C159.2 C162.2 C166.2 C170.1 C172.1 C176.1 C179.2 C185.1 C190.1 C201.2 C202.1 C207.2 C208.1 C211.1 C216.1 C220.1 C221.2 C240.1 C586.2 C592.1 C615.2 C635.1 C667.1 C717.2 C754.2 C770.2 J5.51(VDD1) J5.54(VDD2) J5.57(VDD3) J5.60(VDD4) J5.62(VDD5) J5.65(VDD6) J5.66(VDD7) J5.69(VDD8) J5.72(VDD9) J5.75(VDD10) J5.78(VDD11) J5.170(VDD12) J5.173(VDD13) J5.176(VDD14) J5.179(VDD15) J5.182(VDD16) J5.183(VDD17) J5.186(VDD18) J5.189(VDD19) J5.191(VDD20) J5.194(VDD21) J5.197(VDD22) J7.51(VDD1) J7.54(VDD2) J7.57(VDD3) J7.60(VDD4) J7.62(VDD5) J7.65(VDD6) J7.66(VDD7) J7.69(VDD8) J7.72(VDD9) J7.75(VDD10) J7.78(VDD11) J7.170(VDD12) J7.173(VDD13) J7.176(VDD14) J7.179(VDD15) J7.182(VDD16) J7.183(VDD17) J7.186(VDD18) J7.189(VDD19) J7.191(VDD20) J7.194(VDD21) J7.197(VDD22) R233.2 ; also on sheet 11 13 20 28 29 30 31
GVDD_SENSE: R233.1 ; also on sheet 11
GVSS_SENSE: R234.1 ; also on sheet 11
I2C1_SCL: J5.118(SCL) J7.118(SCL) ; also on sheet 8 12 24 31 50 51 53
I2C1_SDA: J5.238(SDA) J7.238(SDA) ; also on sheet 8 12 24 31 50 51 53
IFC_A0: TP200.1(TP) U593.2(1Q1)
IFC_A1: TP201.1(TP) U593.3(1Q2)
IFC_A2: TP202.1(TP) U593.5(1Q3)
IFC_A3: TP203.1(TP) U593.6(1Q4)
IFC_A4: TP204.1(TP) U593.8(1Q5)
IFC_A5: U593.9(1Q6) U598.1(B)
IFC_A6: U593.11(1Q7) U596.1(B)
IFC_A7: U593.12(1Q8) U595.1(B)
IFC_A8: U37.2(A22) U593.13(2Q1)
IFC_A9: U37.15(A21) U593.14(2Q2)
IFC_A10: U37.12(A20) U593.16(2Q3)
IFC_A11: U37.11(A19) U593.17(2Q4)
IFC_A12: U37.18(A18) U593.19(2Q5)
IFC_A13: U37.19(A17) U593.20(2Q6)
IFC_A14: U37.54(A16) U593.22(2Q7)
IFC_A15: U37.3(A15) U593.23(2Q8)
IFC_A16: U37.4(A14) U594.2(1Q1)
IFC_A17: U37.5(A13) U594.3(1Q2)
IFC_A18: U37.6(A12) U594.5(1Q3)
IFC_A19: U37.7(A11) U594.6(1Q4)
IFC_A20: U37.8(A10) U594.8(1Q5)
IFC_A21: U37.9(A9) U594.9(1Q6)
IFC_A22: U37.10(A8) U594.11(1Q7)
IFC_A23: U37.20(A7) U594.12(1Q8)
IFC_A24: U37.21(A6) U594.13(2Q1)
IFC_A25: U37.22(A5) U594.14(2Q2)
IFC_A26: U22.B40(IFC_A26) U37.23(A4)
IFC_A27: U22.A40(IFC_A27) U37.24(A3)
IFC_A28: U22.D39(IFC_A28) U37.25(A2)
IFC_A29: U22.C39(IFC_A29) U37.26(A1)
IFC_A30: U22.A39(IFC_A30) U37.31(A0)
IFC_A31: TP258.1(TP) U22.C38(IFC_A31)
IFC_AD0: U22.W39(IFC_AD00) U37.51(DQ15/A-1) U38.J8(I/O7) U593.47(1D1) ; also on sheet 8
IFC_AD1: U22.W40(IFC_AD01) U37.49(DQ14) U38.K7(I/O6) U593.46(1D2) ; also on sheet 8
IFC_AD2: U22.V39(IFC_AD02) U37.47(DQ13) U38.J7(I/O5) U593.44(1D3) ; also on sheet 8
IFC_AD3: U22.V40(IFC_AD03) U37.45(DQ12) U38.K6(I/O4) U593.43(1D4) ; also on sheet 8
IFC_AD4: U22.U40(IFC_AD04) U37.42(DQ11) U38.K5(I/O3) U593.41(1D5) ; also on sheet 8
IFC_AD5: U22.U41(IFC_AD05) U37.40(DQ10) U38.K4(I/O2) U593.40(1D6) ; also on sheet 8
IFC_AD6: U22.T39(IFC_AD06) U37.38(DQ9) U38.J4(I/O1) U593.38(1D7) ; also on sheet 8
IFC_AD7: U22.T40(IFC_AD07) U37.36(DQ8) U38.H4(I/O0) U593.37(1D8) ; also on sheet 8
IFC_AD8: U22.R39(IFC_AD08) U37.50(DQ7) U593.36(2D1) ; also on sheet 8
IFC_AD9: U22.R40(IFC_AD09) U37.48(DQ6) U593.35(2D2) ; also on sheet 8
IFC_AD10: U22.P40(IFC_AD10) U37.46(DQ5) U593.33(2D3) ; also on sheet 8
IFC_AD11: U22.P41(IFC_AD11) U37.44(DQ4) U593.32(2D4) ; also on sheet 8
IFC_AD12: U22.N39(IFC_AD12) U37.41(DQ3) U593.30(2D5) ; also on sheet 8
IFC_AD13: U22.N40(IFC_AD13) U37.39(DQ2) U593.29(2D6) ; also on sheet 8
IFC_AD14: U22.M39(IFC_AD14) U37.37(DQ1) U593.27(2D7) ; also on sheet 8
IFC_AD15: U22.M40(IFC_AD15) U37.35(DQ0) U593.26(2D8) ; also on sheet 8
IFC_AD16: U22.L40(IFC_AD16) U594.47(1D1) ; also on sheet 8
IFC_AD17: U22.L41(IFC_AD17) U594.46(1D2) ; also on sheet 8 10
IFC_AD18: U22.K39(IFC_AD18) U594.44(1D3) ; also on sheet 10
IFC_AD19: U22.K40(IFC_AD19) U594.43(1D4) ; also on sheet 10
IFC_AD20: U22.J39(IFC_AD20) U594.41(1D5) ; also on sheet 10
IFC_AD21: U22.J40(IFC_AD21) U594.40(1D6) ; also on sheet 8 10
IFC_AD22: U22.H40(IFC_AD22) U594.38(1D7)
IFC_AD23: U22.H41(IFC_AD23) U594.37(1D8)
IFC_AD24: U22.G40(IFC_AD24) U594.36(2D1)
IFC_AD25: U22.G41(IFC_AD25) U594.35(2D2)
IFC_AD26: U22.G39(IFC_AD26) U594.33(2D3)
IFC_AD27: U22.F40(IFC_AD27) U594.32(2D4)
IFC_AD28: U22.E41(IFC_AD28) U594.30(2D5)
IFC_AD29: U22.E40(IFC_AD29) U594.29(2D6)
IFC_AD30: U22.E39(IFC_AD30) U594.27(2D7)
IFC_AD31: U22.D41(IFC_AD31) U594.26(2D8)
IFC_AVD: U22.H44(IFC_AVD) U38.C4(ALE) U593.25(2LE) U593.48(1LE) U594.25(2LE) U594.48(1LE) ; also on sheet 8
IFC_BCTL: U22.G44(IFC_BCTL) ; also on sheet 8
IFC_CLE: U22.E43(IFC_CLE) U38.D5(CLE) ; also on sheet 8
IFC_CLK: U22.B38(IFC_CLK0) ; also on sheet 8
IFC_CS0_B: R280.2 U22.C43(~{IFC_CS0}) ; also on sheet 8
IFC_CS1_B: R279.2 U22.C44(~{IFC_CS1}) ; also on sheet 8
IFC_CS2_B: R294.2 U22.B43(~{IFC_CS2}) ; also on sheet 8
IFC_CS3_B: R295.2 U22.A42(~{IFC_CS3}) ; also on sheet 8
IFC_CS_B4: TP15.1(TP) U22.C41(~{IFC_CS4})
IFC_CS_B5: TP20.1(TP) U22.B41(~{IFC_CS5})
IFC_CS_B6: TP21.1(TP) U22.A41(~{IFC_CS6})
IFC_CS_B7: TP16.1(TP) U22.C40(~{IFC_CS7})
IFC_NAND_CS_B: R524.2 U38.C6(~{CE}) ; also on sheet 8
IFC_NAND_RB_B: R818.2 U38.C8(R/~{B}) ; also on sheet 8
IFC_NAND_WE_B: R525.2 U38.C7(~{WE}) ; also on sheet 8
IFC_NOR_CS_B: U37.32(~{CE}) ; also on sheet 8
IFC_NOR_RB_B: R5858.2 U37.17(RY/~{BY}) ; also on sheet 8
IFC_NOR_WE_B: U37.13(~{WE}) ; also on sheet 8
IFC_OE_B: U22.E42(~{IFC_OE}) U37.34(~{OE}) U38.D4(~{RE}) ; also on sheet 8
IFC_RB0_B: R276.2 U22.F43(~{IFC_RB0}) ; also on sheet 8
IFC_RB1_B: R277.2 U22.F42(~{IFC_RB1}) ; also on sheet 8
IFC_TE: U22.G42(IFC_TE) ; also on sheet 8
IFC_VBANK0: U37.1(A23) U595.4(Y)
IFC_VBANK1: U37.56(A24) U596.4(Y)
IFC_VBANK2: U37.55(A25) U598.4(Y)
IFC_WE0_B: U22.E44(~{IFC_WE0}) ; also on sheet 8
IFC_WE2_B: TP13.1(TP) U22.D42(~{IFC_WE2}) ; also on sheet 8
IFC_WE3_B: TP14.1(TP) U22.D44(~{IFC_WE3})
IFC_WP_B: U22.F44(~{IFC_WP0}) U37.16(~{WP}/ACC) U38.C3(~{WP}) ; also on sheet 8
ISOSDHC_CLK: R614.1 U45.8(CLKB)
ISOSDHC_CMD: CN3.2(CMD) U45.13(CMDB)
ISOSDHC_DAT0: CN3.7(DAT0) U45.10(DAT0B)
ISOSDHC_DAT1: CN3.8(DAT1) U45.9(DAT1B)
ISOSDHC_DAT2: CN3.9(DAT2) U45.12(DAT2B)
ISOSDHC_DAT3: CN3.1(CD/DAT3) U45.11(DAT3B)
M2_MA0: J7.188(A0) ; also on sheet 29
M2_MA1: J7.181(A1) ; also on sheet 29
M2_MA2: J7.61(A2) ; also on sheet 29
M2_MA3: J7.180(A3) ; also on sheet 29
M2_MA4: J7.59(A4) ; also on sheet 29
M2_MA5: J7.58(A5) ; also on sheet 29
M2_MA6: J7.178(A6) ; also on sheet 29
M2_MA7: J7.56(A7) ; also on sheet 29
M2_MA8: J7.177(A8) ; also on sheet 29
M2_MA9: J7.175(A9) ; also on sheet 29
M2_MA10: J7.70(A10_AP) ; also on sheet 29
M2_MA11: J7.55(A11) ; also on sheet 29
M2_MA12: J7.174(A12_BC) ; also on sheet 29
M2_MA13: J7.196(A13) ; also on sheet 29
M2_MA14: J7.172(A14) ; also on sheet 29
M2_MA15: J7.171(A15) ; also on sheet 29
M2_MBA0: J7.71(BA0) ; also on sheet 29
M2_MBA1: J7.190(BA1) ; also on sheet 29
M2_MBA2: J7.52(BA2) ; also on sheet 29
M2_MCAS_B: J7.74(CAS_L) ; also on sheet 29
M2_MCKE0: J7.50(CKE0) ; also on sheet 29
M2_MCKE1: J7.169(CKE1) ; also on sheet 29
M2_MCLK0_N: J7.185(~{CK0}) ; also on sheet 29
M2_MCLK0_P: J7.184(CK0_P) ; also on sheet 29
M2_MCLK1_N: J7.64(CK1_N_NC2) ; also on sheet 29
M2_MCLK1_P: J7.63(CK1_P_NC1) ; also on sheet 29
M2_MCS_B0: J7.193(S0_L) ; also on sheet 29
M2_MCS_B1: J7.76(S1_L) ; also on sheet 29
M2_MCS_B2: J7.79(NC5_S2_L) ; also on sheet 29
M2_MCS_B3: J7.198(NC6_S3_L) ; also on sheet 29
M2_MDQ0: J7.3(DQ00) ; also on sheet 29
M2_MDQ1: J7.4(DQ01) ; also on sheet 29
M2_MDQ2: J7.9(DQ02) ; also on sheet 29
M2_MDQ3: J7.10(DQ03) ; also on sheet 29
M2_MDQ4: J7.122(DQ04) ; also on sheet 29
M2_MDQ5: J7.123(DQ05) ; also on sheet 29
M2_MDQ6: J7.128(DQ06) ; also on sheet 29
M2_MDQ7: J7.129(DQ07) ; also on sheet 29
M2_MDQ8: J7.12(DQ08) ; also on sheet 29
M2_MDQ9: J7.13(DQ09) ; also on sheet 29
M2_MDQ10: J7.18(DQ10) ; also on sheet 29
M2_MDQ11: J7.19(DQ11) ; also on sheet 29
M2_MDQ12: J7.131(DQ12) ; also on sheet 29
M2_MDQ13: J7.132(DQ13) ; also on sheet 29
M2_MDQ14: J7.137(DQ14) ; also on sheet 29
M2_MDQ15: J7.138(DQ15) ; also on sheet 29
M2_MDQ16: J7.21(DQ16) ; also on sheet 29
M2_MDQ17: J7.22(DQ17) ; also on sheet 29
M2_MDQ18: J7.27(DQ18) ; also on sheet 29
M2_MDQ19: J7.28(DQ19) ; also on sheet 29
M2_MDQ20: J7.140(DQ20) ; also on sheet 29
M2_MDQ21: J7.141(DQ21) ; also on sheet 29
M2_MDQ22: J7.146(DQ22) ; also on sheet 29
M2_MDQ23: J7.147(DQ23) ; also on sheet 29
M2_MDQ24: J7.30(DQ24) ; also on sheet 29
M2_MDQ25: J7.31(DQ25) ; also on sheet 29
M2_MDQ26: J7.36(DQ26) ; also on sheet 29
M2_MDQ27: J7.37(DQ27) ; also on sheet 29
M2_MDQ28: J7.149(DQ28) ; also on sheet 29
M2_MDQ29: J7.150(DQ29) ; also on sheet 29
M2_MDQ30: J7.155(DQ30) ; also on sheet 29
M2_MDQ31: J7.156(DQ31) ; also on sheet 29
M2_MDQ32: J7.81(DQ32) ; also on sheet 29
M2_MDQ33: J7.82(DQ33) ; also on sheet 29
M2_MDQ34: J7.87(DQ34) ; also on sheet 29
M2_MDQ35: J7.88(DQ35) ; also on sheet 29
M2_MDQ36: J7.200(DQ36) ; also on sheet 29
M2_MDQ37: J7.201(DQ37) ; also on sheet 29
M2_MDQ38: J7.206(DQ38) ; also on sheet 29
M2_MDQ39: J7.207(DQ39) ; also on sheet 29
M2_MDQ40: J7.90(DQ40) ; also on sheet 29
M2_MDQ41: J7.91(DQ41) ; also on sheet 29
M2_MDQ42: J7.96(DQ42) ; also on sheet 29
M2_MDQ43: J7.97(DQ43) ; also on sheet 29
M2_MDQ44: J7.209(DQ44) ; also on sheet 29
M2_MDQ45: J7.210(DQ45) ; also on sheet 29
M2_MDQ46: J7.215(DQ46) ; also on sheet 29
M2_MDQ47: J7.216(DQ47) ; also on sheet 29
M2_MDQ48: J7.99(DQ48) ; also on sheet 29
M2_MDQ49: J7.100(DQ49) ; also on sheet 29
M2_MDQ50: J7.105(DQ50) ; also on sheet 29
M2_MDQ51: J7.106(DQ51) ; also on sheet 29
M2_MDQ52: J7.218(DQ52) ; also on sheet 29
M2_MDQ53: J7.219(DQ53) ; also on sheet 29
M2_MDQ54: J7.224(DQ54) ; also on sheet 29
M2_MDQ55: J7.225(DQ55) ; also on sheet 29
M2_MDQ56: J7.108(DQ56) ; also on sheet 29
M2_MDQ57: J7.109(DQ57) ; also on sheet 29
M2_MDQ58: J7.114(DQ58) ; also on sheet 29
M2_MDQ59: J7.115(DQ59) ; also on sheet 29
M2_MDQ60: J7.227(DQ60) ; also on sheet 29
M2_MDQ61: J7.228(DQ61) ; also on sheet 29
M2_MDQ62: J7.233(DQ62) ; also on sheet 29
M2_MDQ63: J7.234(DQ63) ; also on sheet 29
M2_MDQS_N0: J7.6(~{DQS0}) ; also on sheet 29
M2_MDQS_N1: J7.15(~{DQS1}) ; also on sheet 29
M2_MDQS_N2: J7.24(~{DQS2}) ; also on sheet 29
M2_MDQS_N3: J7.33(~{DQS3}) ; also on sheet 29
M2_MDQS_N4: J7.84(~{DQS4}) ; also on sheet 29
M2_MDQS_N5: J7.93(~{DQS5}) ; also on sheet 29
M2_MDQS_N6: J7.102(~{DQS6}) ; also on sheet 29
M2_MDQS_N7: J7.111(~{DQS7}) ; also on sheet 29
M2_MDQS_N8: J7.42(~{DQS8}) ; also on sheet 29
M2_MDQS_N9: J7.126(~{NC7_DQS9}) ; also on sheet 29
M2_MDQS_N10: J7.135(~{NC8_DQS10}) ; also on sheet 29
M2_MDQS_N11: J7.144(~{NC9_DQS11}) ; also on sheet 29
M2_MDQS_N12: J7.153(~{NC10_DQS12}) ; also on sheet 29
M2_MDQS_N13: J7.204(~{NC11_DQS13}) ; also on sheet 29
M2_MDQS_N14: J7.213(~{NC12_DQS14}) ; also on sheet 29
M2_MDQS_N15: J7.222(~{NC13_DQS15}) ; also on sheet 29
M2_MDQS_N16: J7.231(~{NC14_DQS16}) ; also on sheet 29
M2_MDQS_N17: J7.162(~{NC15_DQS17}) ; also on sheet 29
M2_MDQS_P0: J7.7(DQS0_P) ; also on sheet 29
M2_MDQS_P1: J7.16(DQS1_P) ; also on sheet 29
M2_MDQS_P2: J7.25(DQS2_P) ; also on sheet 29
M2_MDQS_P3: J7.34(DQS3_P) ; also on sheet 29
M2_MDQS_P4: J7.85(DQS4_P) ; also on sheet 29
M2_MDQS_P5: J7.94(DQS5_P) ; also on sheet 29
M2_MDQS_P6: J7.103(DQS6_P) ; also on sheet 29
M2_MDQS_P7: J7.112(DQS7_P) ; also on sheet 29
M2_MDQS_P8: J7.43(DQS8_P) ; also on sheet 29
M2_MDQS_P9: J7.125(DM0_DQS9_P) ; also on sheet 29
M2_MDQS_P10: J7.134(DM1_DQS10_P) ; also on sheet 29
M2_MDQS_P11: J7.143(DM2_DQS11_P) ; also on sheet 29
M2_MDQS_P12: J7.152(DM3_DQS12_P) ; also on sheet 29
M2_MDQS_P13: J7.203(DM4_DQS13_P) ; also on sheet 29
M2_MDQS_P14: J7.212(DM5_DQS14_P) ; also on sheet 29
M2_MDQS_P15: J7.221(DM6_DQS15_P) ; also on sheet 29
M2_MDQS_P16: J7.230(DM7_DQS16_P) ; also on sheet 29
M2_MDQS_P17: J7.161(DM8_DQS17_P) ; also on sheet 29
M2_MECC0: J7.39(CB0) ; also on sheet 29
M2_MECC1: J7.40(CB1) ; also on sheet 29
M2_MECC2: J7.45(CB2) ; also on sheet 29
M2_MECC3: J7.46(CB3) ; also on sheet 29
M2_MECC4: J7.158(CB4) ; also on sheet 29
M2_MECC5: J7.159(CB5) ; also on sheet 29
M2_MECC6: J7.164(CB6) ; also on sheet 29
M2_MECC7: J7.165(CB7) ; also on sheet 29
M2_MODT0: J7.195(ODT0) ; also on sheet 29
M2_MODT1: J7.77(ODT1) ; also on sheet 29
M2_MRAS_B: J7.192(RAS_L) ; also on sheet 29
M2_MWE_B: J7.73(WE_L) ; also on sheet 29
M2_PARERR_B: J7.53(NC17_ERROUT_L) ; also on sheet 29
M2_PAROUT: J7.68(NC16_PARIN_L) ; also on sheet 29
M3_MA0: J5.188(A0) ; also on sheet 30
M3_MA1: J5.181(A1) ; also on sheet 30
M3_MA2: J5.61(A2) ; also on sheet 30
M3_MA3: J5.180(A3) ; also on sheet 30
M3_MA4: J5.59(A4) ; also on sheet 30
M3_MA5: J5.58(A5) ; also on sheet 30
M3_MA6: J5.178(A6) ; also on sheet 30
M3_MA7: J5.56(A7) ; also on sheet 30
M3_MA8: J5.177(A8) ; also on sheet 30
M3_MA9: J5.175(A9) ; also on sheet 30
M3_MA10: J5.70(A10_AP) ; also on sheet 30
M3_MA11: J5.55(A11) ; also on sheet 30
M3_MA12: J5.174(A12_BC) ; also on sheet 30
M3_MA13: J5.196(A13) ; also on sheet 30
M3_MA14: J5.172(A14) ; also on sheet 30
M3_MA15: J5.171(A15) ; also on sheet 30
M3_MBA0: J5.71(BA0) ; also on sheet 30
M3_MBA1: J5.190(BA1) ; also on sheet 30
M3_MBA2: J5.52(BA2) ; also on sheet 30
M3_MCAS_B: J5.74(CAS_L) ; also on sheet 30
M3_MCKE0: J5.50(CKE0) ; also on sheet 30
M3_MCKE1: J5.169(CKE1) ; also on sheet 30
M3_MCLK0_N: J5.185(~{CK0}) ; also on sheet 30
M3_MCLK0_P: J5.184(CK0_P) ; also on sheet 30
M3_MCLK1_N: J5.64(CK1_N_NC2) ; also on sheet 30
M3_MCLK1_P: J5.63(CK1_P_NC1) ; also on sheet 30
M3_MCS_B0: J5.193(S0_L) ; also on sheet 30
M3_MCS_B1: J5.76(S1_L) ; also on sheet 30
M3_MCS_B2: J5.79(NC5_S2_L) ; also on sheet 30
M3_MCS_B3: J5.198(NC6_S3_L) ; also on sheet 30
M3_MDQ0: J5.3(DQ00) ; also on sheet 30
M3_MDQ1: J5.4(DQ01) ; also on sheet 30
M3_MDQ2: J5.9(DQ02) ; also on sheet 30
M3_MDQ3: J5.10(DQ03) ; also on sheet 30
M3_MDQ4: J5.122(DQ04) ; also on sheet 30
M3_MDQ5: J5.123(DQ05) ; also on sheet 30
M3_MDQ6: J5.128(DQ06) ; also on sheet 30
M3_MDQ7: J5.129(DQ07) ; also on sheet 30
M3_MDQ8: J5.12(DQ08) ; also on sheet 30
M3_MDQ9: J5.13(DQ09) ; also on sheet 30
M3_MDQ10: J5.18(DQ10) ; also on sheet 30
M3_MDQ11: J5.19(DQ11) ; also on sheet 30
M3_MDQ12: J5.131(DQ12) ; also on sheet 30
M3_MDQ13: J5.132(DQ13) ; also on sheet 30
M3_MDQ14: J5.137(DQ14) ; also on sheet 30
M3_MDQ15: J5.138(DQ15) ; also on sheet 30
M3_MDQ16: J5.21(DQ16) ; also on sheet 30
M3_MDQ17: J5.22(DQ17) ; also on sheet 30
M3_MDQ18: J5.27(DQ18) ; also on sheet 30
M3_MDQ19: J5.28(DQ19) ; also on sheet 30
M3_MDQ20: J5.140(DQ20) ; also on sheet 30
M3_MDQ21: J5.141(DQ21) ; also on sheet 30
M3_MDQ22: J5.146(DQ22) ; also on sheet 30
M3_MDQ23: J5.147(DQ23) ; also on sheet 30
M3_MDQ24: J5.30(DQ24) ; also on sheet 30
M3_MDQ25: J5.31(DQ25) ; also on sheet 30
M3_MDQ26: J5.36(DQ26) ; also on sheet 30
M3_MDQ27: J5.37(DQ27) ; also on sheet 30
M3_MDQ28: J5.149(DQ28) ; also on sheet 30
M3_MDQ29: J5.150(DQ29) ; also on sheet 30
M3_MDQ30: J5.155(DQ30) ; also on sheet 30
M3_MDQ31: J5.156(DQ31) ; also on sheet 30
M3_MDQ32: J5.81(DQ32) ; also on sheet 30
M3_MDQ33: J5.82(DQ33) ; also on sheet 30
M3_MDQ34: J5.87(DQ34) ; also on sheet 30
M3_MDQ35: J5.88(DQ35) ; also on sheet 30
M3_MDQ36: J5.200(DQ36) ; also on sheet 30
M3_MDQ37: J5.201(DQ37) ; also on sheet 30
M3_MDQ38: J5.206(DQ38) ; also on sheet 30
M3_MDQ39: J5.207(DQ39) ; also on sheet 30
M3_MDQ40: J5.90(DQ40) ; also on sheet 30
M3_MDQ41: J5.91(DQ41) ; also on sheet 30
M3_MDQ42: J5.96(DQ42) ; also on sheet 30
M3_MDQ43: J5.97(DQ43) ; also on sheet 30
M3_MDQ44: J5.209(DQ44) ; also on sheet 30
M3_MDQ45: J5.210(DQ45) ; also on sheet 30
M3_MDQ46: J5.215(DQ46) ; also on sheet 30
M3_MDQ47: J5.216(DQ47) ; also on sheet 30
M3_MDQ48: J5.99(DQ48) ; also on sheet 30
M3_MDQ49: J5.100(DQ49) ; also on sheet 30
M3_MDQ50: J5.105(DQ50) ; also on sheet 30
M3_MDQ51: J5.106(DQ51) ; also on sheet 30
M3_MDQ52: J5.218(DQ52) ; also on sheet 30
M3_MDQ53: J5.219(DQ53) ; also on sheet 30
M3_MDQ54: J5.224(DQ54) ; also on sheet 30
M3_MDQ55: J5.225(DQ55) ; also on sheet 30
M3_MDQ56: J5.108(DQ56) ; also on sheet 30
M3_MDQ57: J5.109(DQ57) ; also on sheet 30
M3_MDQ58: J5.114(DQ58) ; also on sheet 30
M3_MDQ59: J5.115(DQ59) ; also on sheet 30
M3_MDQ60: J5.227(DQ60) ; also on sheet 30
M3_MDQ61: J5.228(DQ61) ; also on sheet 30
M3_MDQ62: J5.233(DQ62) ; also on sheet 30
M3_MDQ63: J5.234(DQ63) ; also on sheet 30
M3_MDQS_N0: J5.6(~{DQS0}) ; also on sheet 30
M3_MDQS_N1: J5.15(~{DQS1}) ; also on sheet 30
M3_MDQS_N2: J5.24(~{DQS2}) ; also on sheet 30
M3_MDQS_N3: J5.33(~{DQS3}) ; also on sheet 30
M3_MDQS_N4: J5.84(~{DQS4}) ; also on sheet 30
M3_MDQS_N5: J5.93(~{DQS5}) ; also on sheet 30
M3_MDQS_N6: J5.102(~{DQS6}) ; also on sheet 30
M3_MDQS_N7: J5.111(~{DQS7}) ; also on sheet 30
M3_MDQS_N8: J5.42(~{DQS8}) ; also on sheet 30
M3_MDQS_N9: J5.126(~{NC7_DQS9}) ; also on sheet 30
M3_MDQS_N10: J5.135(~{NC8_DQS10}) ; also on sheet 30
M3_MDQS_N11: J5.144(~{NC9_DQS11}) ; also on sheet 30
M3_MDQS_N12: J5.153(~{NC10_DQS12}) ; also on sheet 30
M3_MDQS_N13: J5.204(~{NC11_DQS13}) ; also on sheet 30
M3_MDQS_N14: J5.213(~{NC12_DQS14}) ; also on sheet 30
M3_MDQS_N15: J5.222(~{NC13_DQS15}) ; also on sheet 30
M3_MDQS_N16: J5.231(~{NC14_DQS16}) ; also on sheet 30
M3_MDQS_N17: J5.162(~{NC15_DQS17}) ; also on sheet 30
M3_MDQS_P0: J5.7(DQS0_P) ; also on sheet 30
M3_MDQS_P1: J5.16(DQS1_P) ; also on sheet 30
M3_MDQS_P2: J5.25(DQS2_P) ; also on sheet 30
M3_MDQS_P3: J5.34(DQS3_P) ; also on sheet 30
M3_MDQS_P4: J5.85(DQS4_P) ; also on sheet 30
M3_MDQS_P5: J5.94(DQS5_P) ; also on sheet 30
M3_MDQS_P6: J5.103(DQS6_P) ; also on sheet 30
M3_MDQS_P7: J5.112(DQS7_P) ; also on sheet 30
M3_MDQS_P8: J5.43(DQS8_P) ; also on sheet 30
M3_MDQS_P9: J5.125(DM0_DQS9_P) ; also on sheet 30
M3_MDQS_P10: J5.134(DM1_DQS10_P) ; also on sheet 30
M3_MDQS_P11: J5.143(DM2_DQS11_P) ; also on sheet 30
M3_MDQS_P12: J5.152(DM3_DQS12_P) ; also on sheet 30
M3_MDQS_P13: J5.203(DM4_DQS13_P) ; also on sheet 30
M3_MDQS_P14: J5.212(DM5_DQS14_P) ; also on sheet 30
M3_MDQS_P15: J5.221(DM6_DQS15_P) ; also on sheet 30
M3_MDQS_P16: J5.230(DM7_DQS16_P) ; also on sheet 30
M3_MDQS_P17: J5.161(DM8_DQS17_P) ; also on sheet 30
M3_MECC0: J5.39(CB0) ; also on sheet 30
M3_MECC1: J5.40(CB1) ; also on sheet 30
M3_MECC2: J5.45(CB2) ; also on sheet 30
M3_MECC3: J5.46(CB3) ; also on sheet 30
M3_MECC4: J5.158(CB4) ; also on sheet 30
M3_MECC5: J5.159(CB5) ; also on sheet 30
M3_MECC6: J5.164(CB6) ; also on sheet 30
M3_MECC7: J5.165(CB7) ; also on sheet 30
M3_MODT0: J5.195(ODT0) ; also on sheet 30
M3_MODT1: J5.77(ODT1) ; also on sheet 30
M3_MRAS_B: J5.192(RAS_L) ; also on sheet 30
M3_MWE_B: J5.73(WE_L) ; also on sheet 30
M3_PARERR_B: J5.53(NC17_ERROUT_L) ; also on sheet 30
M3_PAROUT: J5.68(NC16_PARIN_L) ; also on sheet 30
M_VREF_A: C35.1 C197.1 J7.1(VREFDQ) J7.67(VREFCA) ; also on sheet 13 28 29 31
M_VREF_B: C27.1 C666.1 J5.1(VREFDQ) J5.67(VREFCA) ; also on sheet 13 30
M_VTT_A: C117.1 C148.1 C303.1 J7.48(NC3_VTT3) J7.49(NC4_VTT4) J7.120(VTT1) J7.240(VTT2) R5905.1 ; also on sheet 13 31
M_VTT_B: C119.1 C300.1 C305.1 J5.48(NC3_VTT3) J5.49(NC4_VTT4) J5.120(VTT1) J5.240(VTT2) R5906.1 ; also on sheet 13
NAND_LOCK: TP222.1(TP) U38.G5(LOCK)
OVDD: C276.1 C341.1 C345.1 C346.1 C347.1 C433.1 C3849.1 C3850.1 C3851.1 C3852.1 C5171.1 C5320.1 R276.1 R277.1 R279.1 R280.1 R294.1 R295.1 R297.1 R298.1 R299.1 R524.1 R525.1 R743.1 R750.1 R758.1 R759.1 R771.1 R772.1 R818.1 R5703.1 R5851.1 R5852.1 R5858.1 U26.8(VDD) U37.29(VIO) U37.43(VCC) U38.D3(VCC1) U38.G4(VCC2) U38.H8(VCC3) U38.J6(VCC4) U45.15(VCCA) U593.7(VCC1) U593.18(VCC2) U593.31(VCC3) U593.42(VCC4) U594.7(VCC1) U594.18(VCC2) U594.31(VCC3) U594.42(VCC4) U595.5(VCC) U596.5(VCC) U598.5(VCC) ; also on sheet 10 11 18 20 21 24 25 27
PROC_IFC_CLK1: TP10.1(TP) U22.H42(IFC_CLK1)
PROC_IFC_CLK2: TP22.1(TP) U22.A38(IFC_CLK2)
PROC_IFC_NDDDR_CLK: TP11.1(TP) U22.H43(IFC_NDDDR_CLK)
PROC_IFC_NDDQS: TP101.1(TP) U22.E36(IFC_NDDQS)
PROC_IFC_PAR0: R759.2 U22.E38(IFC_PAR0)
PROC_IFC_PAR1: R758.2 U22.D38(IFC_PAR1)
PROC_IFC_PAR2: R750.2 U22.F38(IFC_PAR2)
PROC_IFC_PAR3: R772.2 U22.F37(IFC_PAR3)
PROC_IFC_PERR_B: R771.2 U22.E37(~{IFC_PERR})
RST_IFC_B: U37.14(~{RESET}) ; also on sheet 8
RST_MEM_B: J5.168(RESET_L) J7.168(RESET_L) ; also on sheet 8 31
RST_SPI_B: U26.7(~{HOLD}) ; also on sheet 8
SD_CD#: CN3.10(CD_SW) ESD10.1(A1) R637.2
SD_WP: CN3.11(WP) ESD9.1(A1) R667.2
SDCK: C485.1 CN3.5(CLK) R614.2
SDHC_CD_B: R637.1 R5851.2 U22.A34(SDHC_CD_RSVD) ; also on sheet 27
SDHC_CLK: R301.2 U45.5(CLKA)
SDHC_CMD: R743.2 U22.D33(SDHC_CMD) U45.16(CMDA)
SDHC_DAT0: U22.B34(SDHC_DAT0) U45.3(DAT0A)
SDHC_DAT1: U22.C34(SDHC_DAT1) U45.4(DAT1A)
SDHC_DAT2: U22.A35(SDHC_DAT2) U45.1(DAT2A)
SDHC_DAT3: U22.B35(SDHC_DAT3) U45.2(DAT3A)
SDHC_WP: R667.1 R5852.2 U22.C33(SDHC_WP_RSVD) ; also on sheet 27
SDP1_CLKF: TP72.1(TP) U45.6(CLK_FB)
SPI_CE_B: R318.1 U26.1(~{CE})
SPI_CLK: R296.1 R310.1 U26.6(SCK)
SPI_CS0_B: R318.2 U22.C35(~{SPI_CS0})
SPI_CS1_B: TP19.1(TP) U22.A36(~{SPI_CS1})
SPI_CS2_B: TP103.1(TP) U22.C36(~{SPI_CS2})
SPI_CS3_B: TP18.1(TP) U22.D36(~{SPI_CS3})
SPI_MISO: R298.2 U22.C37(SPI_MISO) U26.2(SO/SIO1)
SPI_MOSI: R297.2 U22.A37(SPI_MOSI) U26.5(SI/SIO0)
SPI_WP_B: R299.2 U26.3(~{WP})
UT_SDHCCLK: R301.1 U22.A33(SDHC_CLK)
UT_SPICLK: R296.2 U22.B37(SPI_CLK)
VTT_A_SENSE: R5905.2 ; also on sheet 13
VTT_B_SENSE: R5906.2 ; also on sheet 13
XIFC_A26: TP253.1(TP) U594.16(2Q3)
XIFC_A27: TP254.1(TP) U594.17(2Q4)
XIFC_A28: TP255.1(TP) U594.19(2Q5)
XIFC_A29: TP256.1(TP) U594.20(2Q6)
XIFC_A30: TP257.1(TP) U594.22(2Q7)
XIFC_A31: TP252.1(TP) U594.23(2Q8)
N30954766: R5703.2 U37.53(~{BYTE})

Not connected (* = marked no-connect by the designer): J5 167(NC19_TEST)* 187(NC18_EVENT_L)*; J7 167(NC19_TEST)* 187(NC18_EVENT_L)*; U37 27(NC)* 28(NC)* 30(NC)*; U38 A1(NC23)* A2(NC24)* A9(NC26)* A10(NC27)* B1(NC25)* B9(NC28)* B10(NC29)* D6(NC5)* D7(NC6)* D8(NC7)* E3(NC8)* E4(NC9)* E5(NC10)* E6(NC11)* E7(NC12)* E8(NC13)* F3(NC14)* F4(NC15)* F5(NC16)* F6(NC17)* F8(NC18)* G3(DNU1)* G6(NC19)* G7(NC20)* G8(DNU2)* H3(NC21)* H5(NC22)* H6(NC1)* H7(NC2)* J3(NC3)* J5(NC4)* L1(NC30)* L2(NC31)* L9(NC34)* L10(NC35)* M1(NC32)* M2(NC33)* M9(NC36)* M10(NC37)*

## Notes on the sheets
sheet 32
- DDR3 DIMM #2
- Place near DDR
  Route diff-pair
- SPD ADDR = 0x54
sheet 33
- DDR3 DIMM #3
- SPD ADDR = 0x56
sheet 34
- T4240 IFC Interface
- 1.8V
- 1.8V
- 1.8V
- 1.8V
- 1.8V
- 1.8V
- 1.8V
- 1.8V
- 1.8V
- 1.8V
- 1.8V
- 1.8V
- 1.8V
- 1.8V
- 1.8V
- 1.8V
- OVDD
- 1.8V
- NOR FLASH
  VIRTUAL BANK
- 1.8V
- 1.8V
- IFC LSBs are
  provided by the
  T4240
sheet 35
- NOR & NAND Flash
- NOR FLASH
  128MB
- 1.8V
- 1.8V
- 1.8V
- OVDD
- NAND FLASH
  8Gb/1GB
  IND type is shown,
  COM + AUTO are permitted.
sheet 36
- SPI & SD Card Interface
- OVDD
- OVDD:1.8V
- OVDD:1.8V
- OVDD:1.8V
- NOTE: Keep UT_SPICLK and UT_SDHCCLK
              traces short (<2 cm)
- 1.8V
- 1.8V
- 1.8V
- 1.8V
- 1.8V
